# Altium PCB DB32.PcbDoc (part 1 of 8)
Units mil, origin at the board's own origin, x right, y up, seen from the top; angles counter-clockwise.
Board outline 3236.22 x 4456.69 mil, 8 copper layers (Top Layer, MidLayer1, MidLayer2, GND-Layer5, MidLayer3, VCC, MidLayer4, Bottom Layer), stack 61.8 mil thick; 207 components, 474 nets, 1777 pads, 1474 vias.
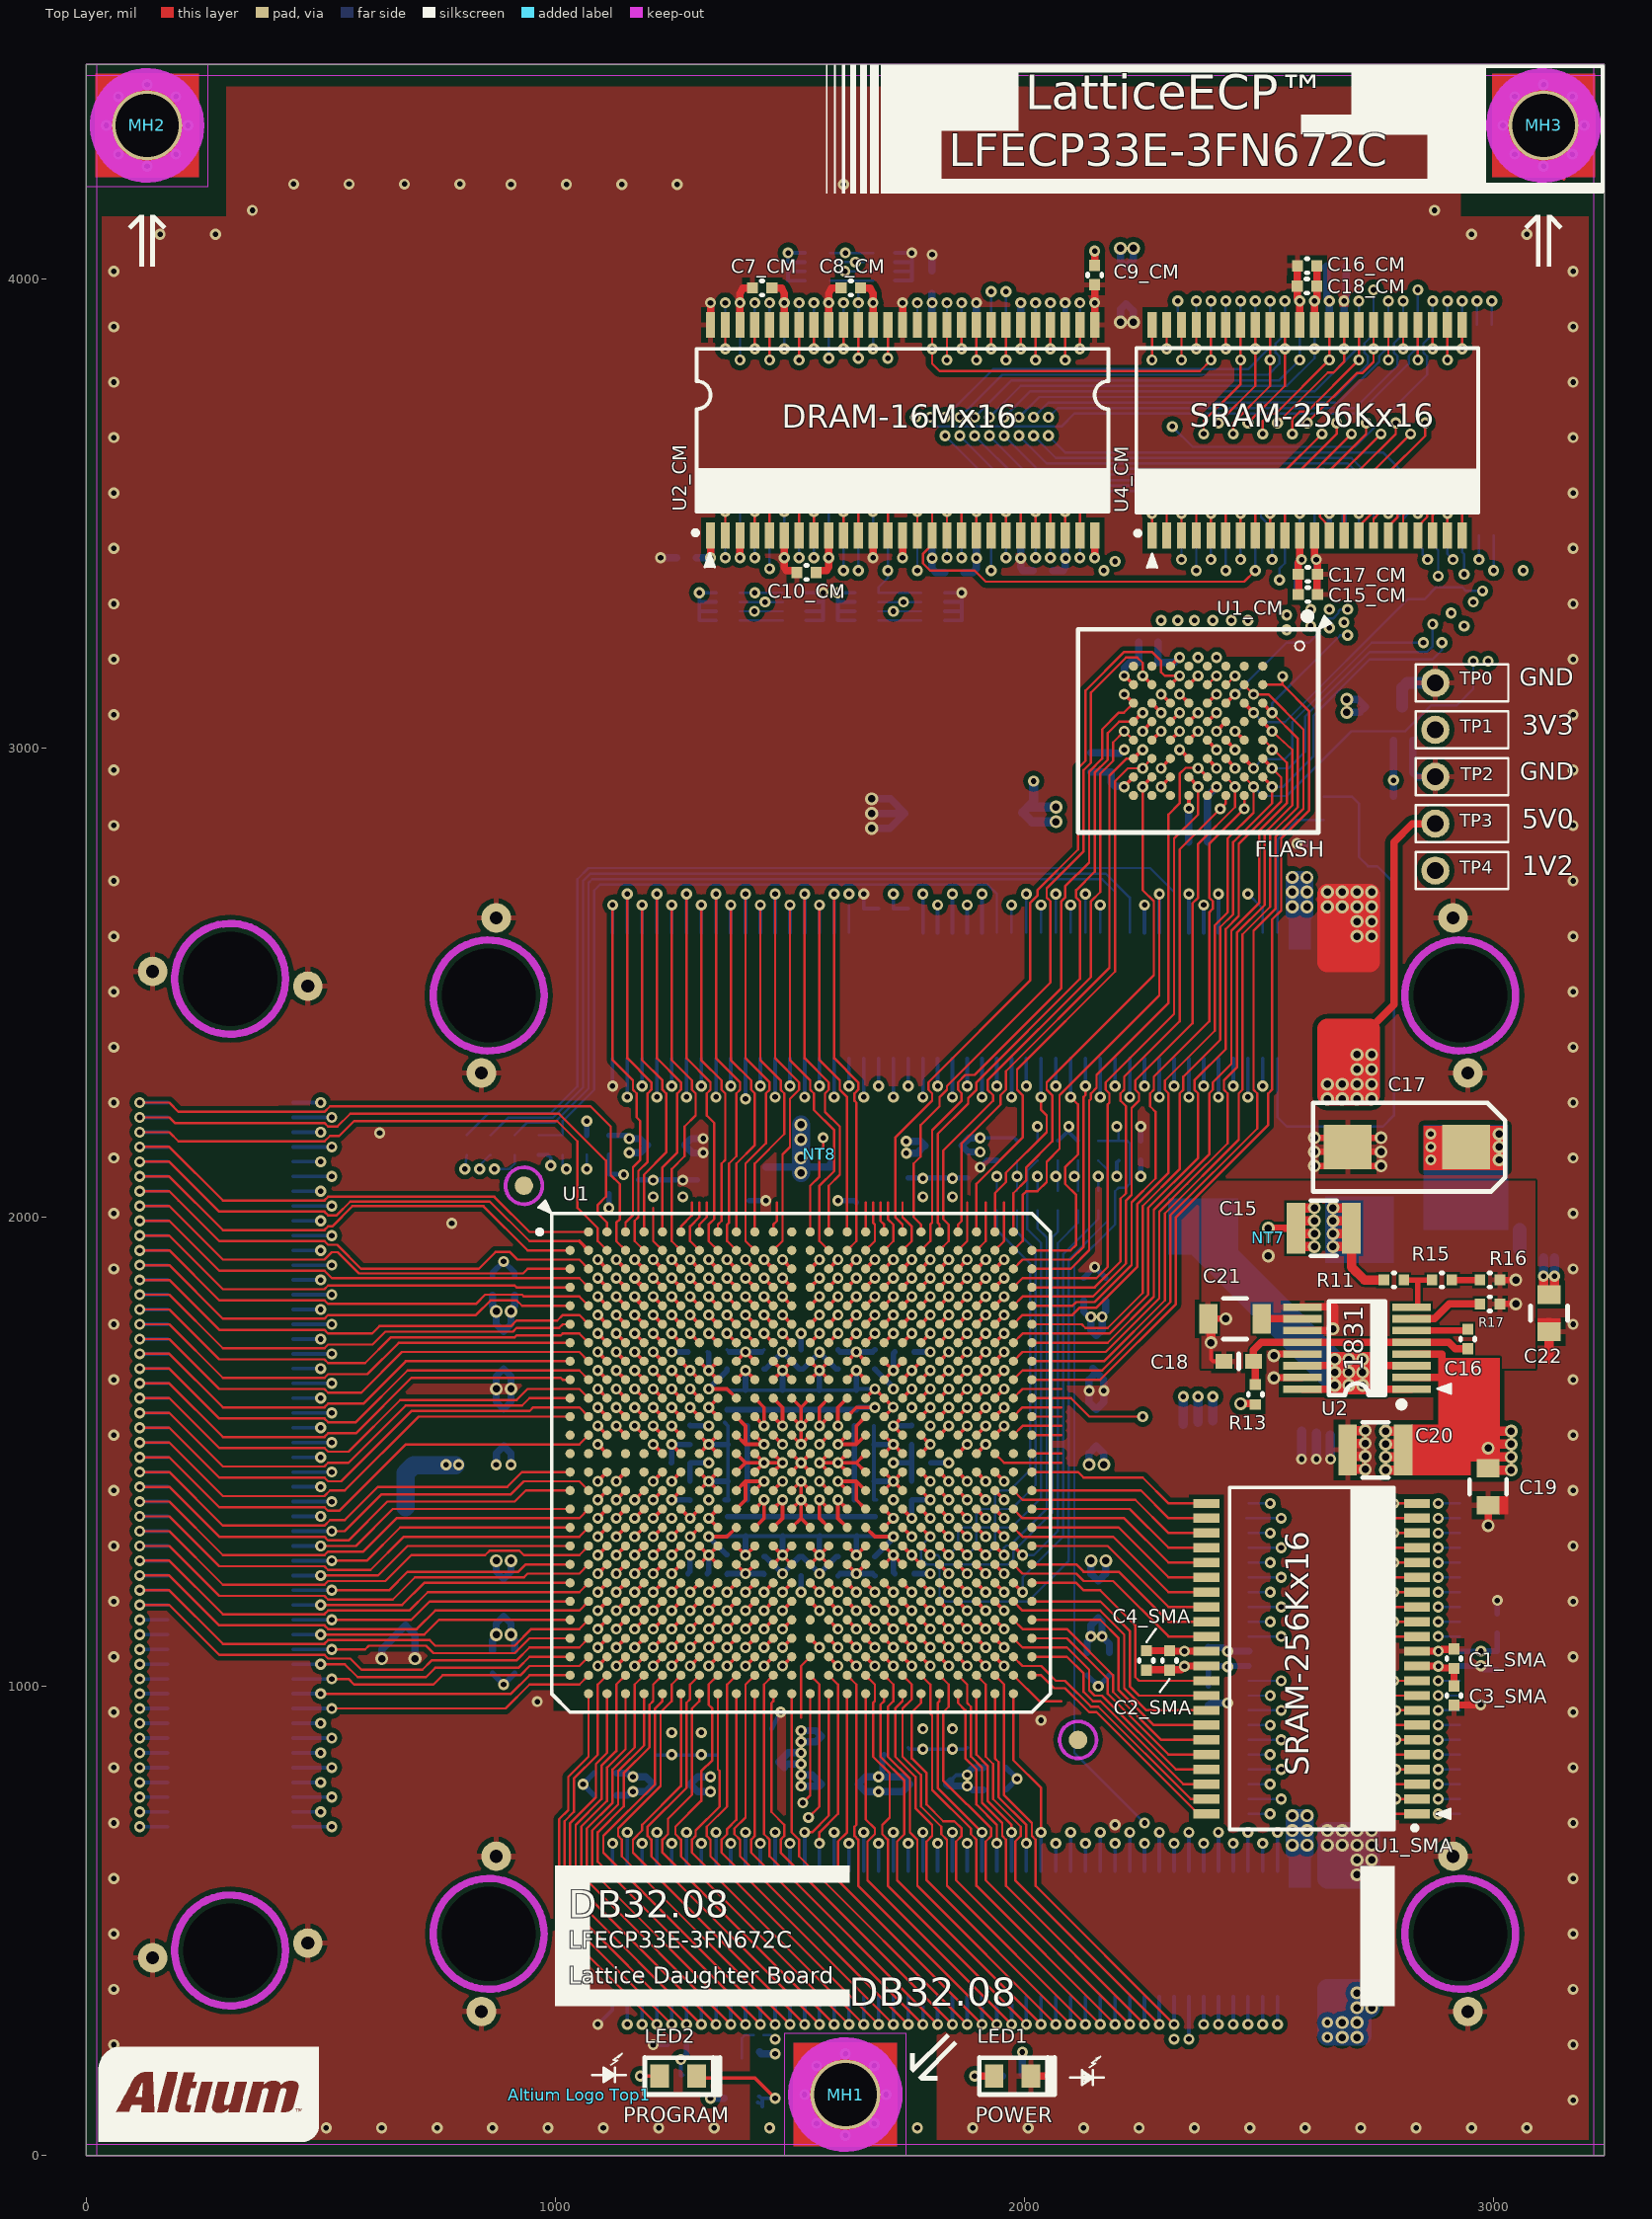
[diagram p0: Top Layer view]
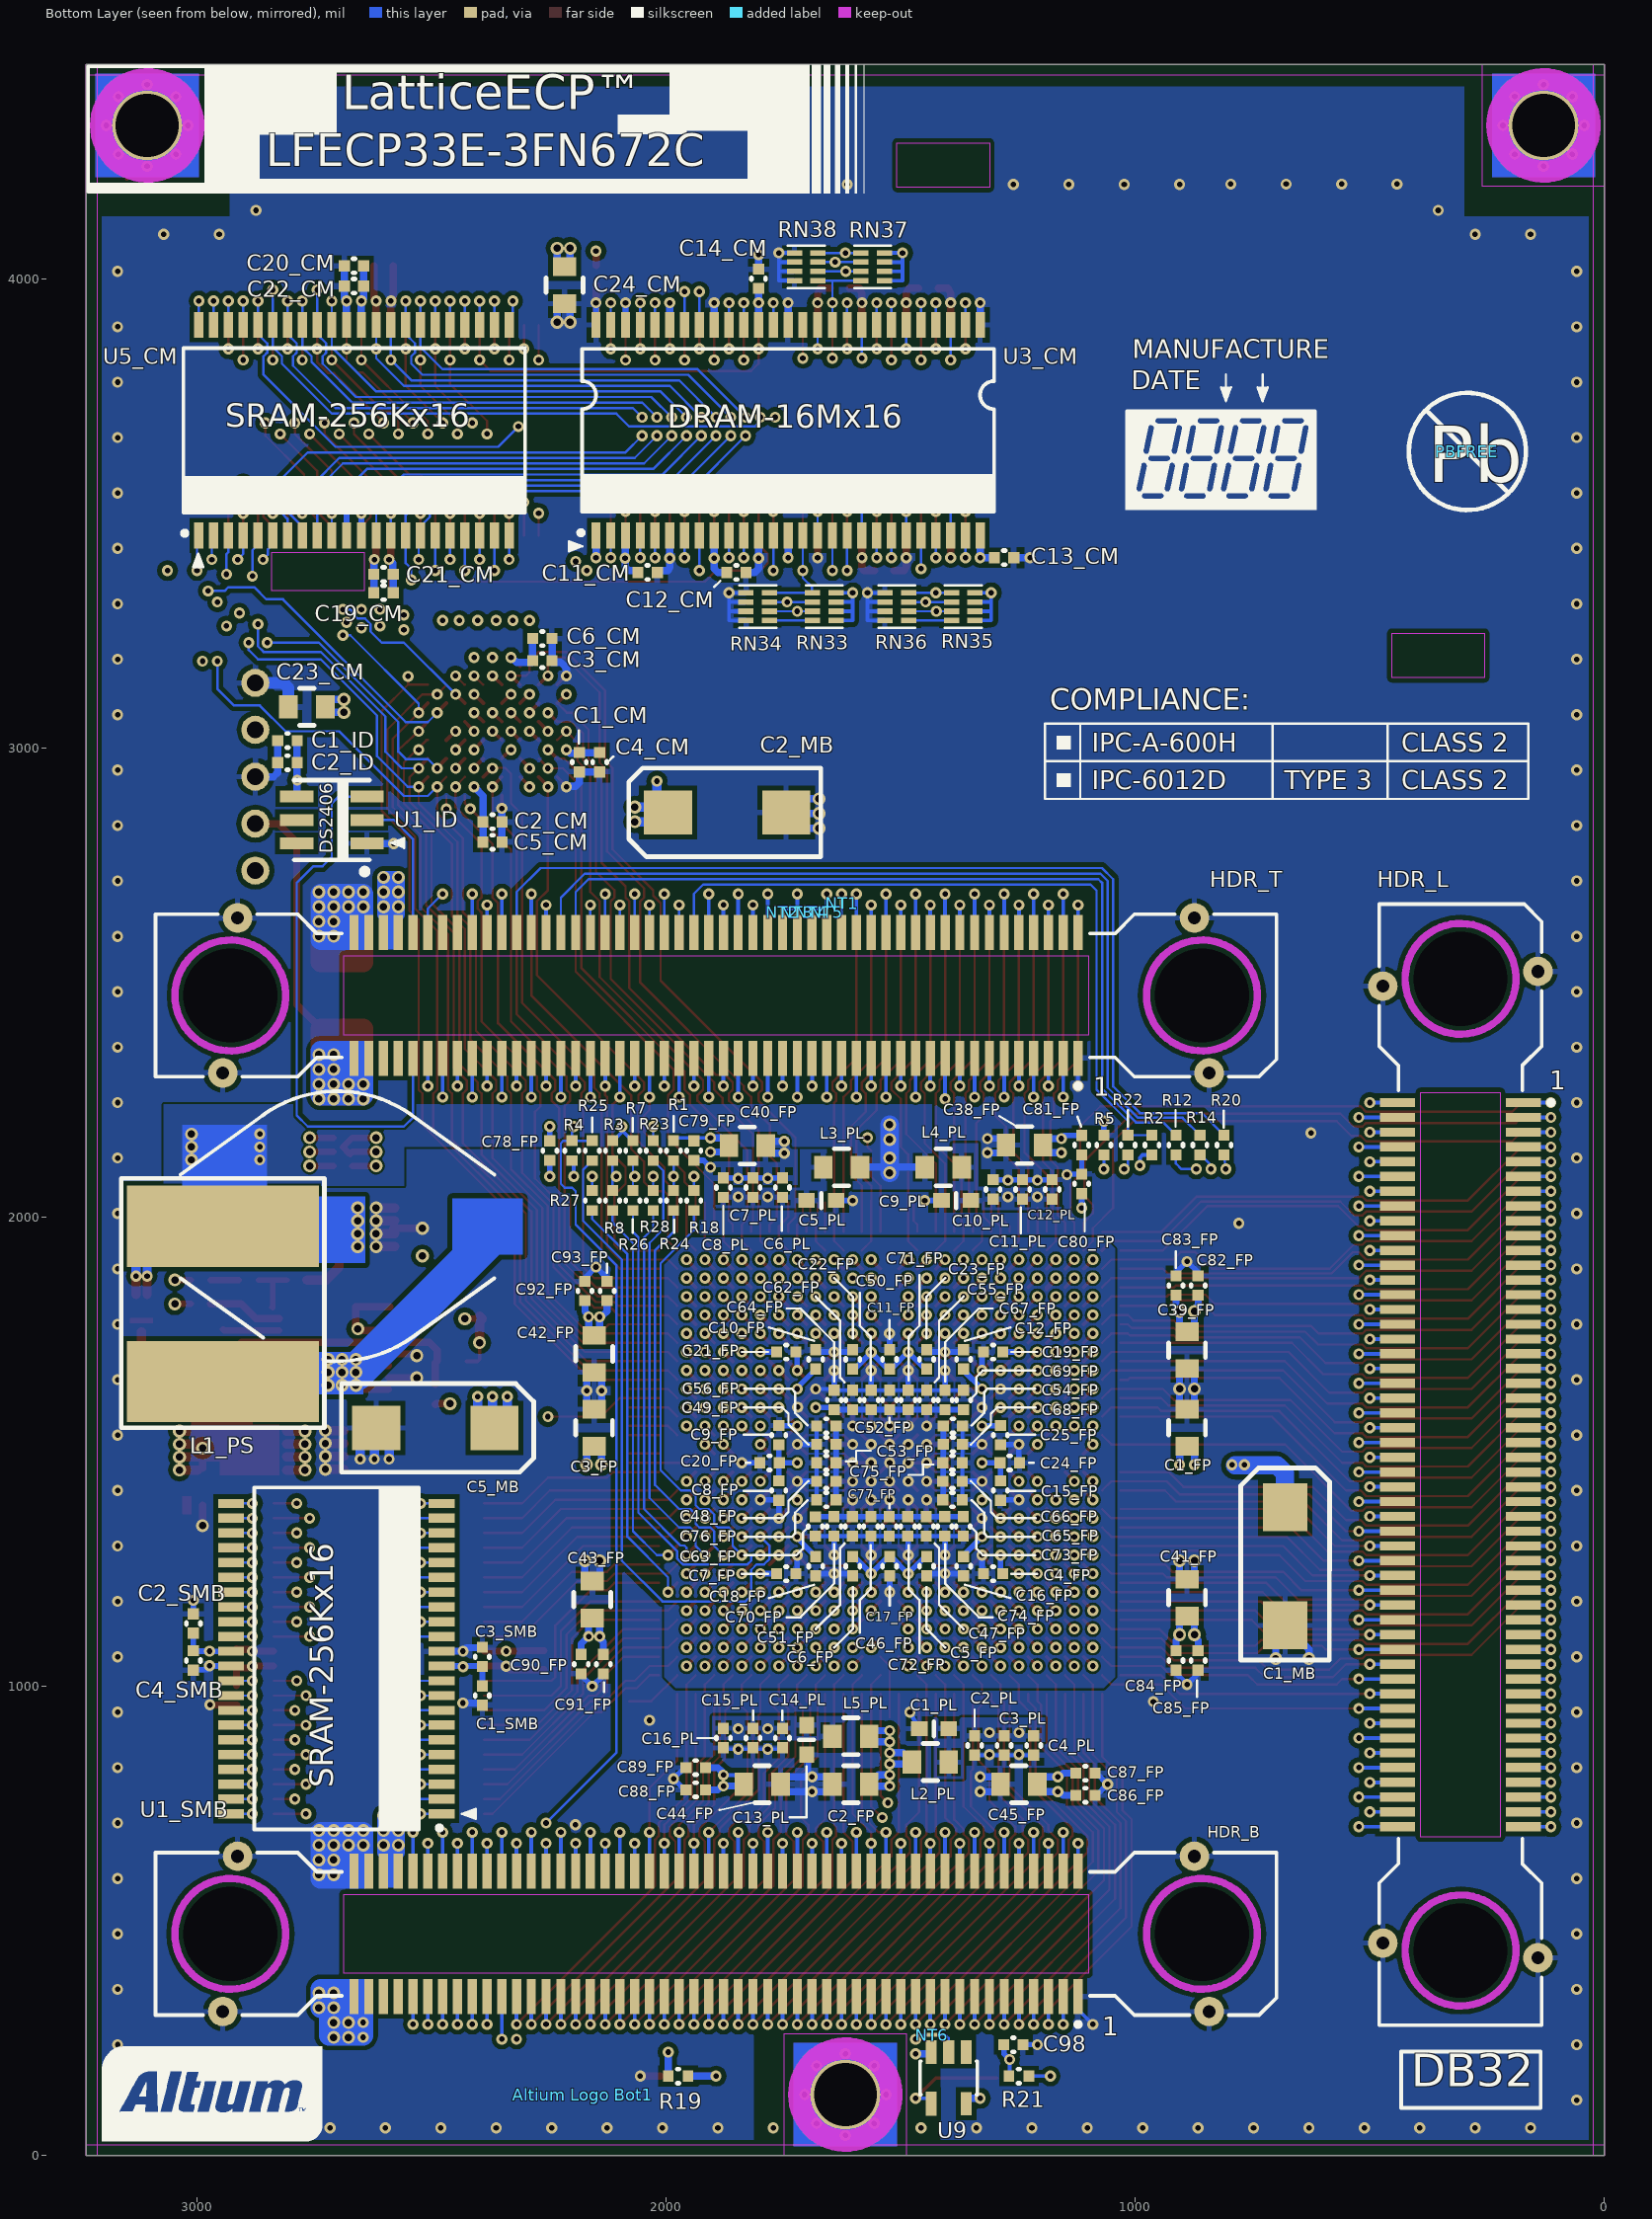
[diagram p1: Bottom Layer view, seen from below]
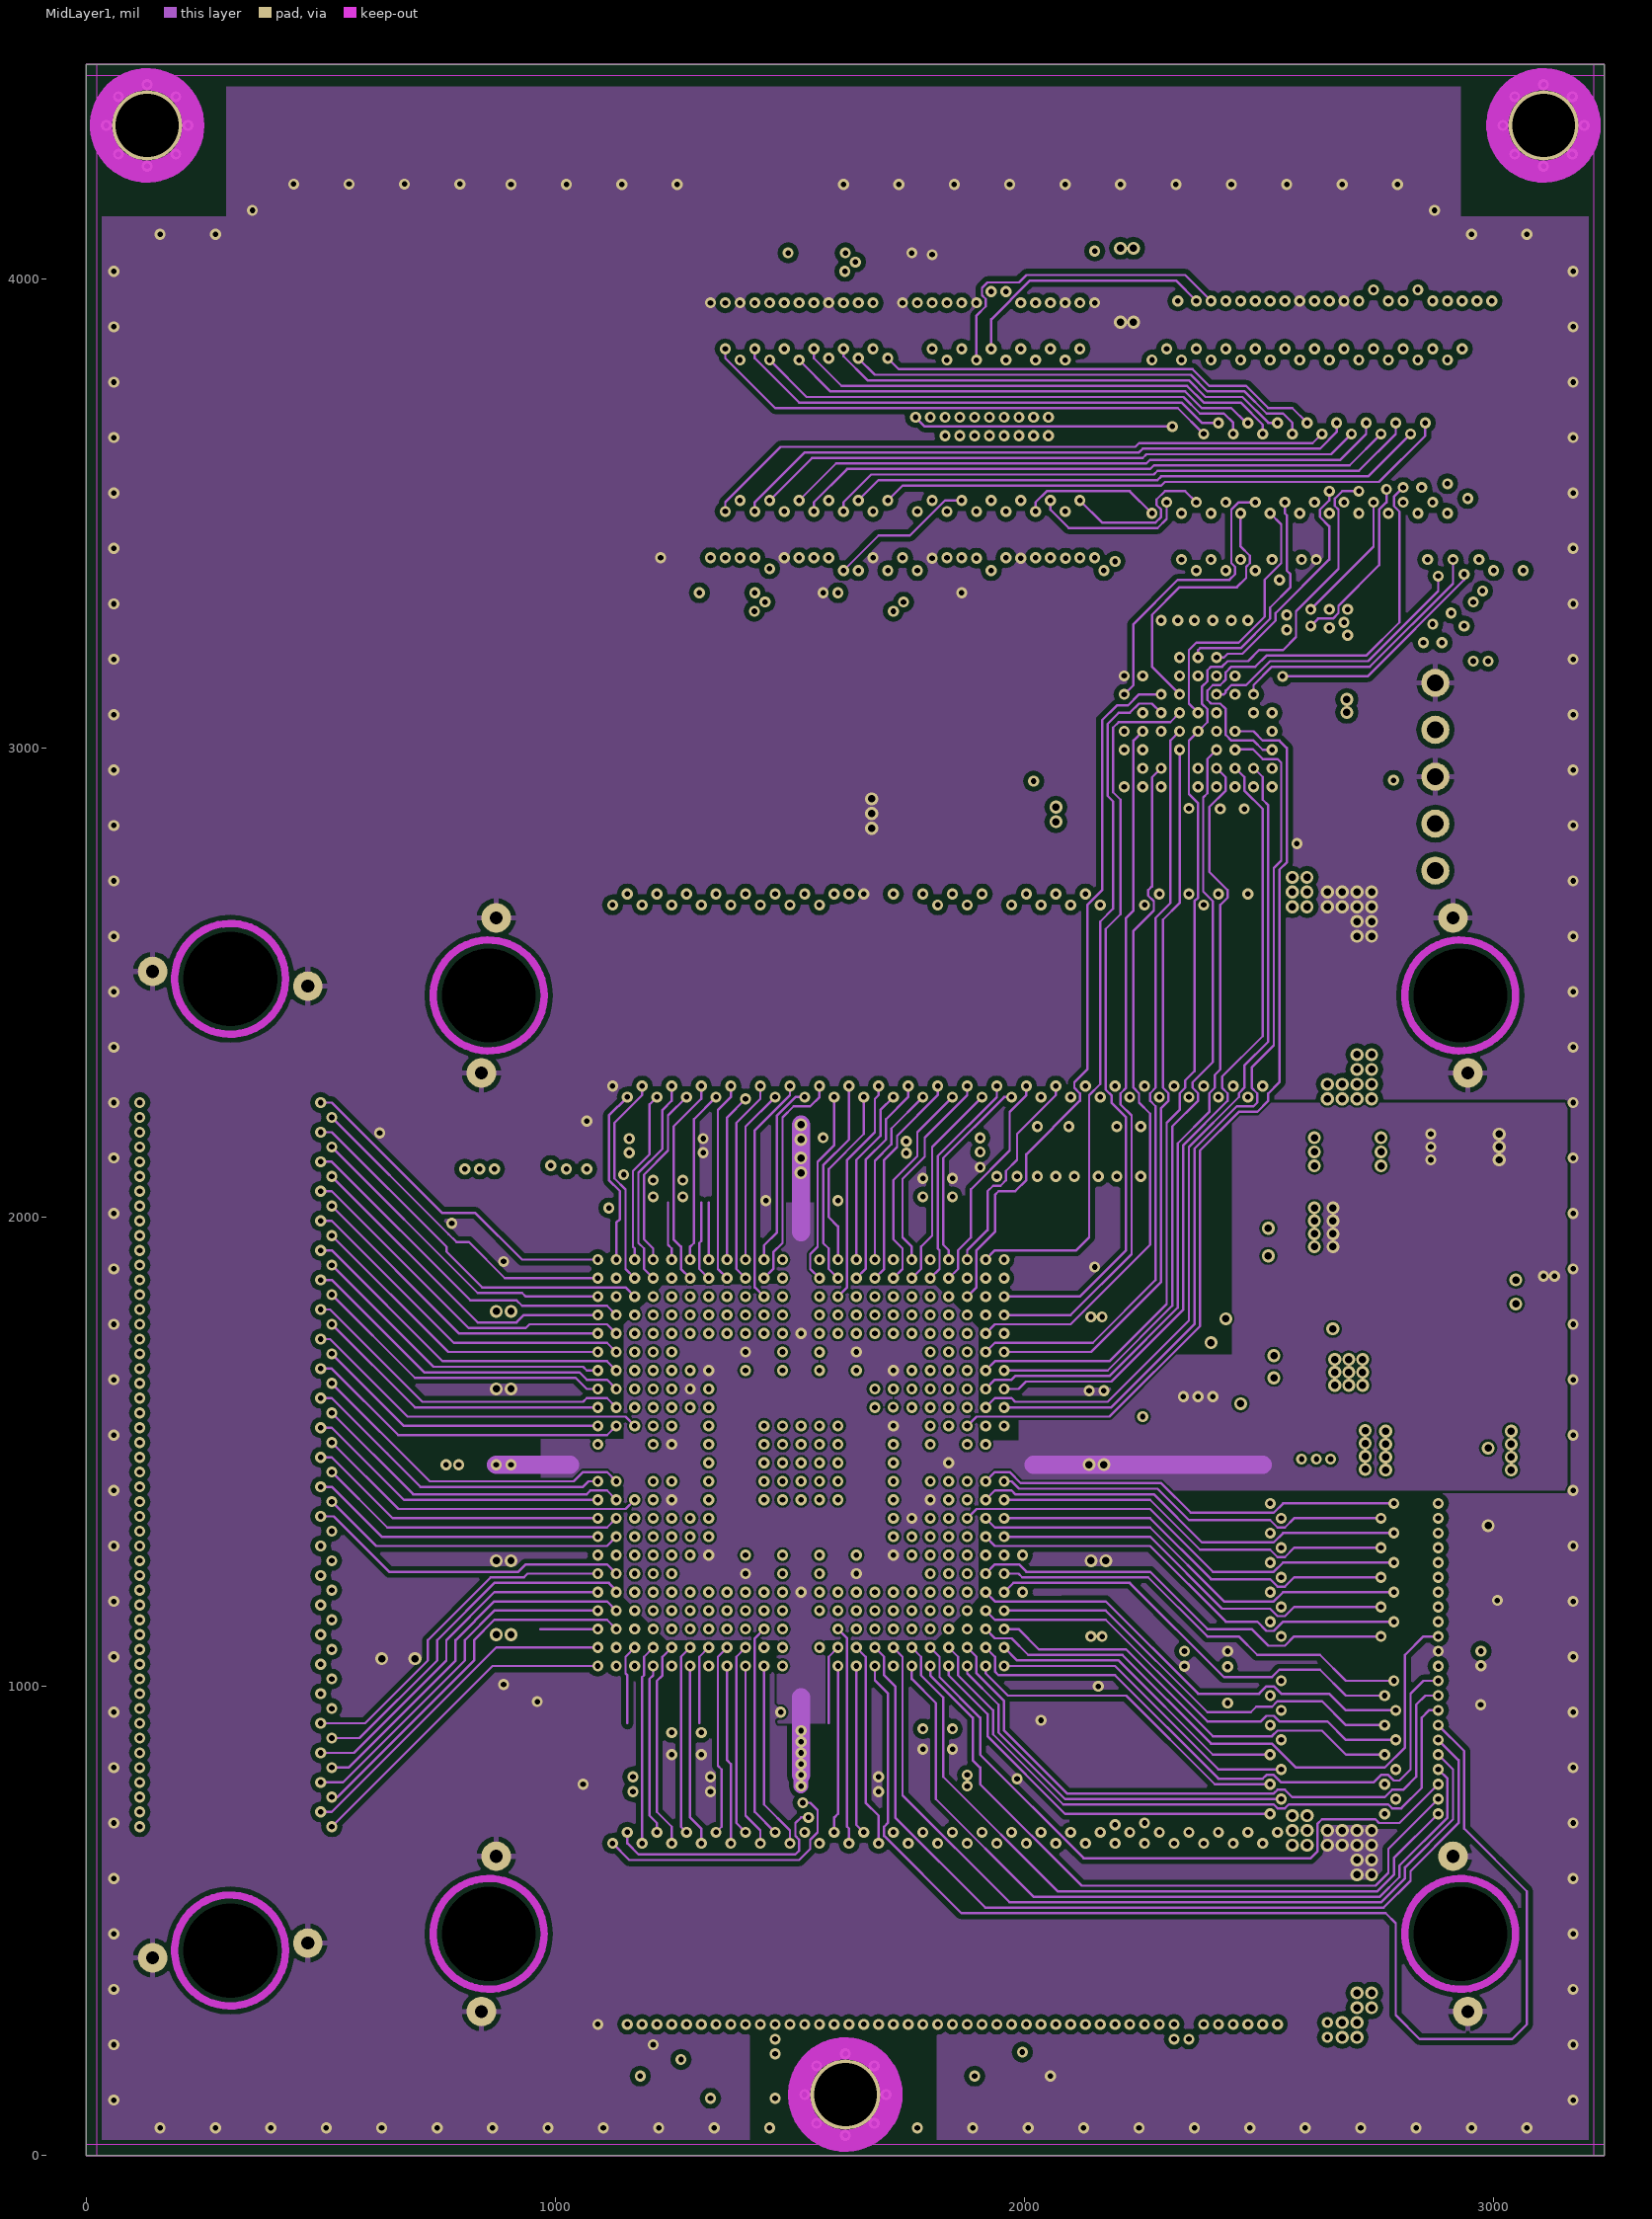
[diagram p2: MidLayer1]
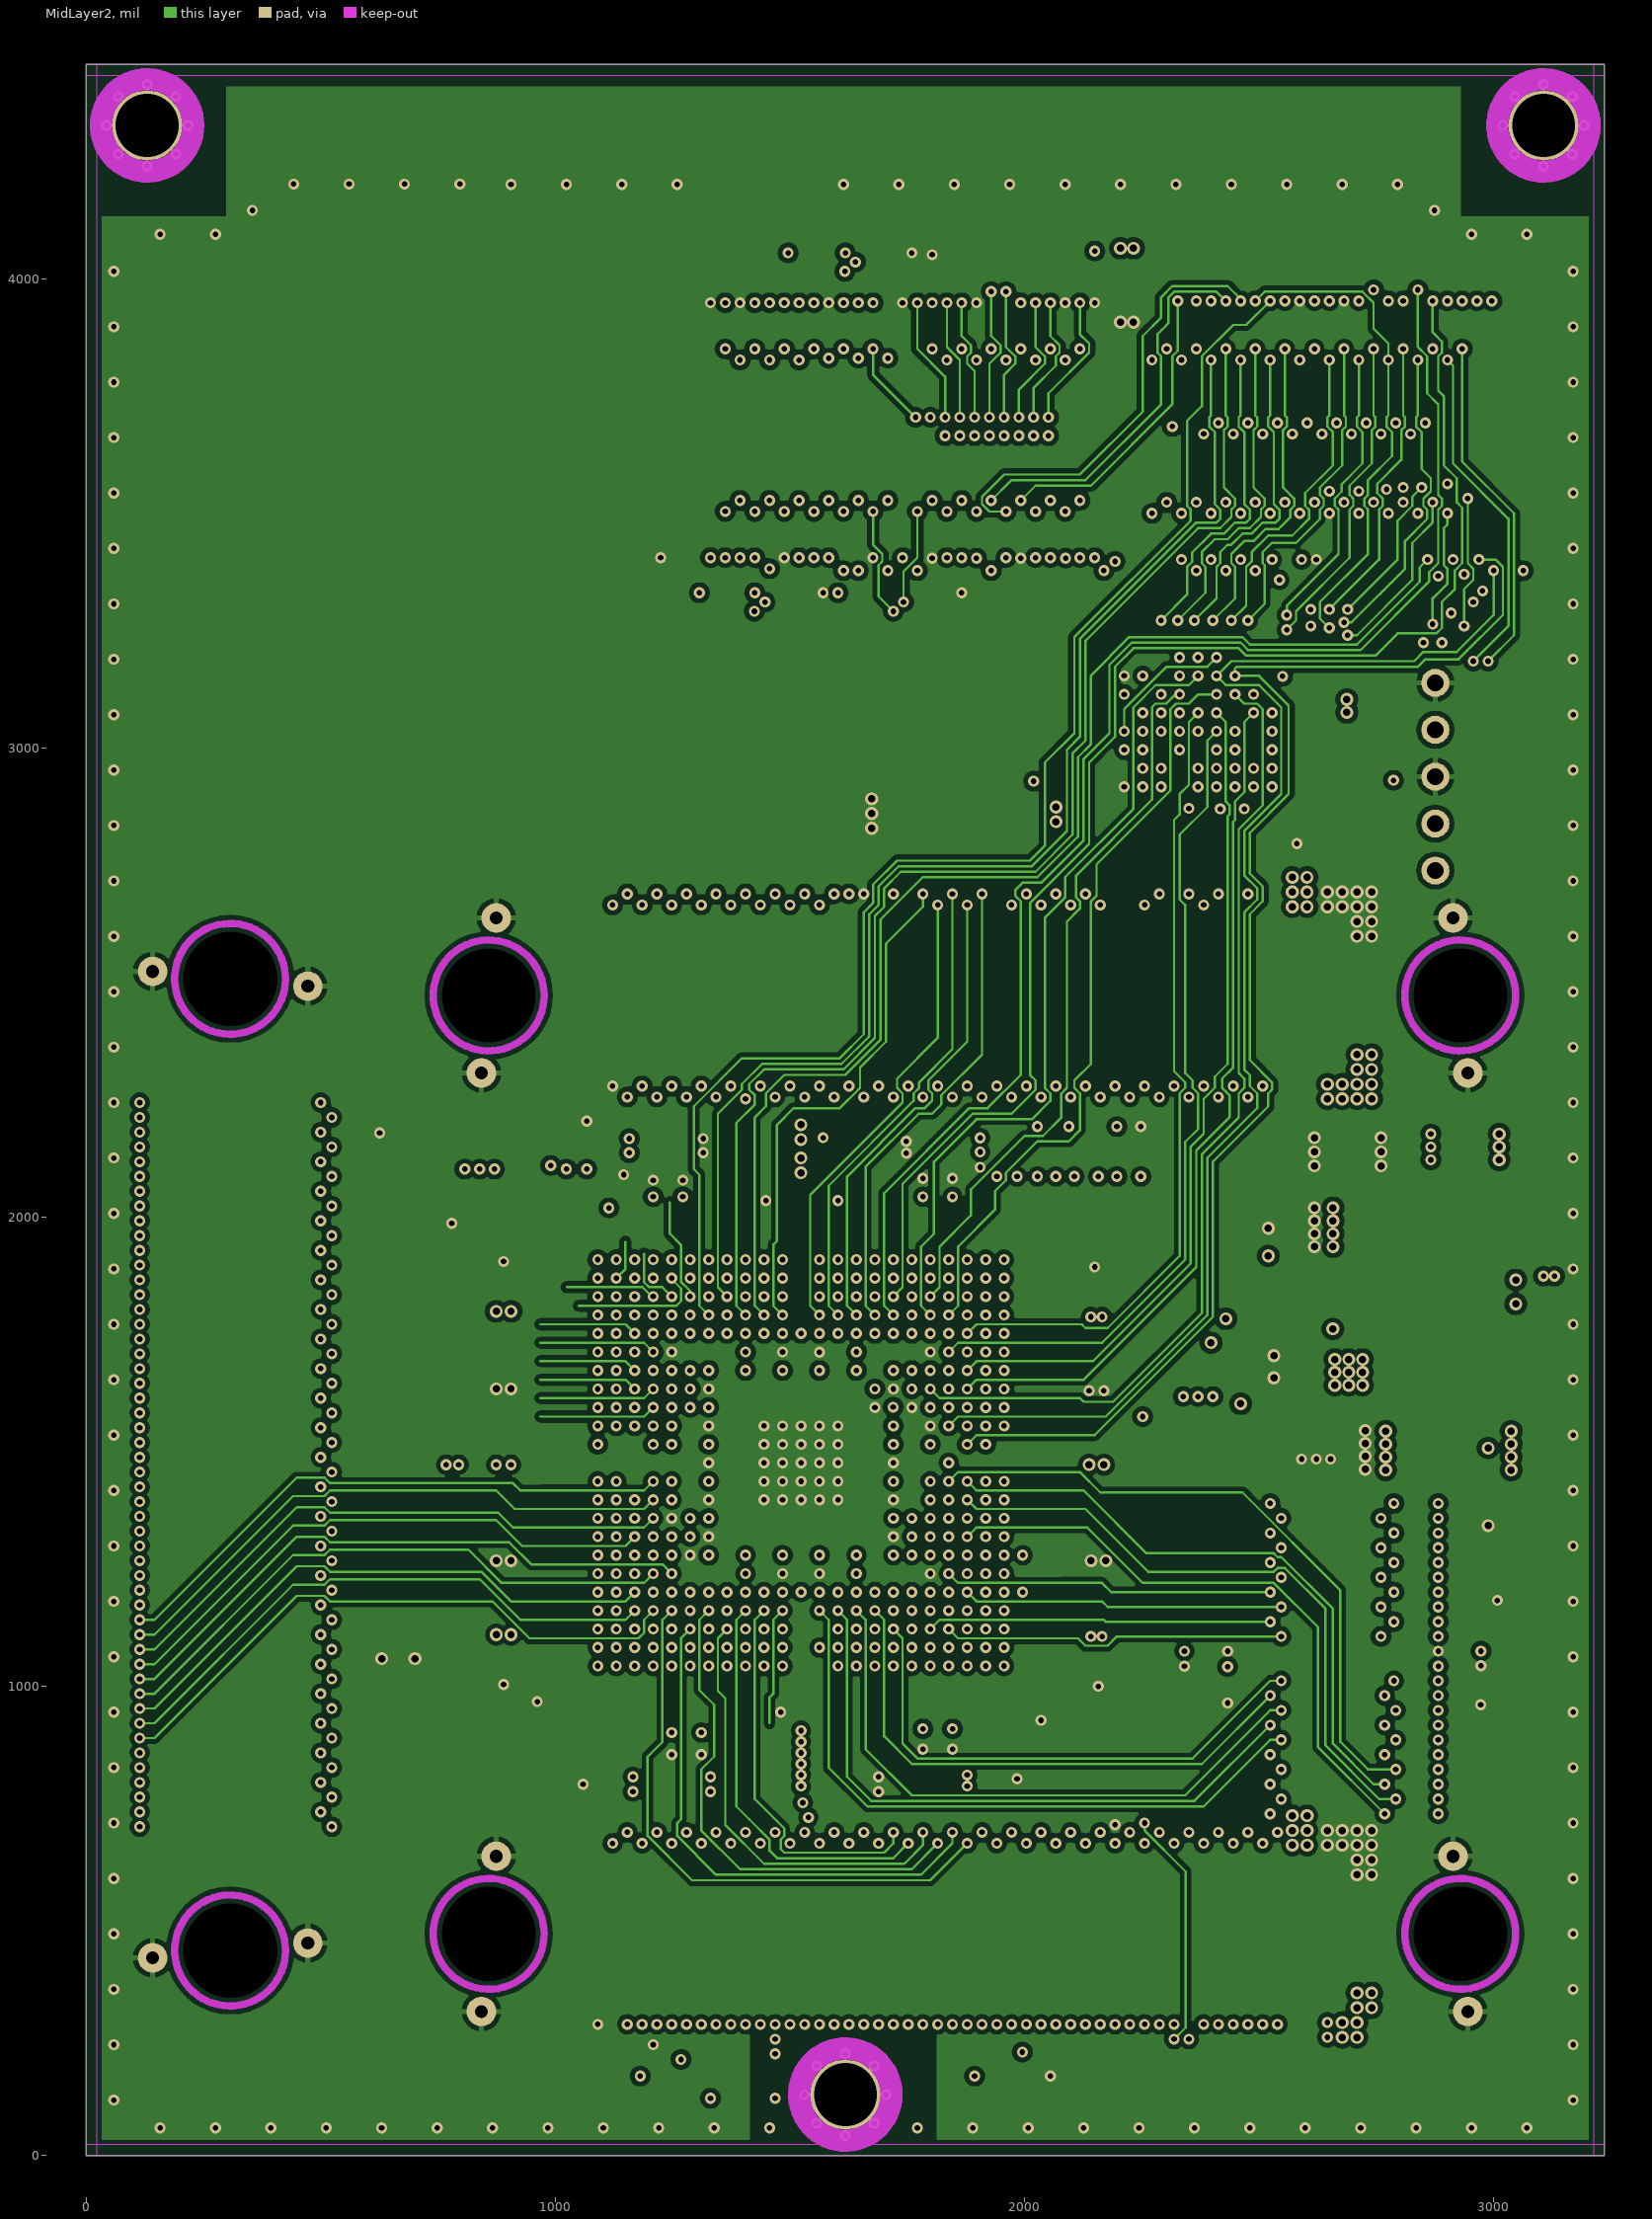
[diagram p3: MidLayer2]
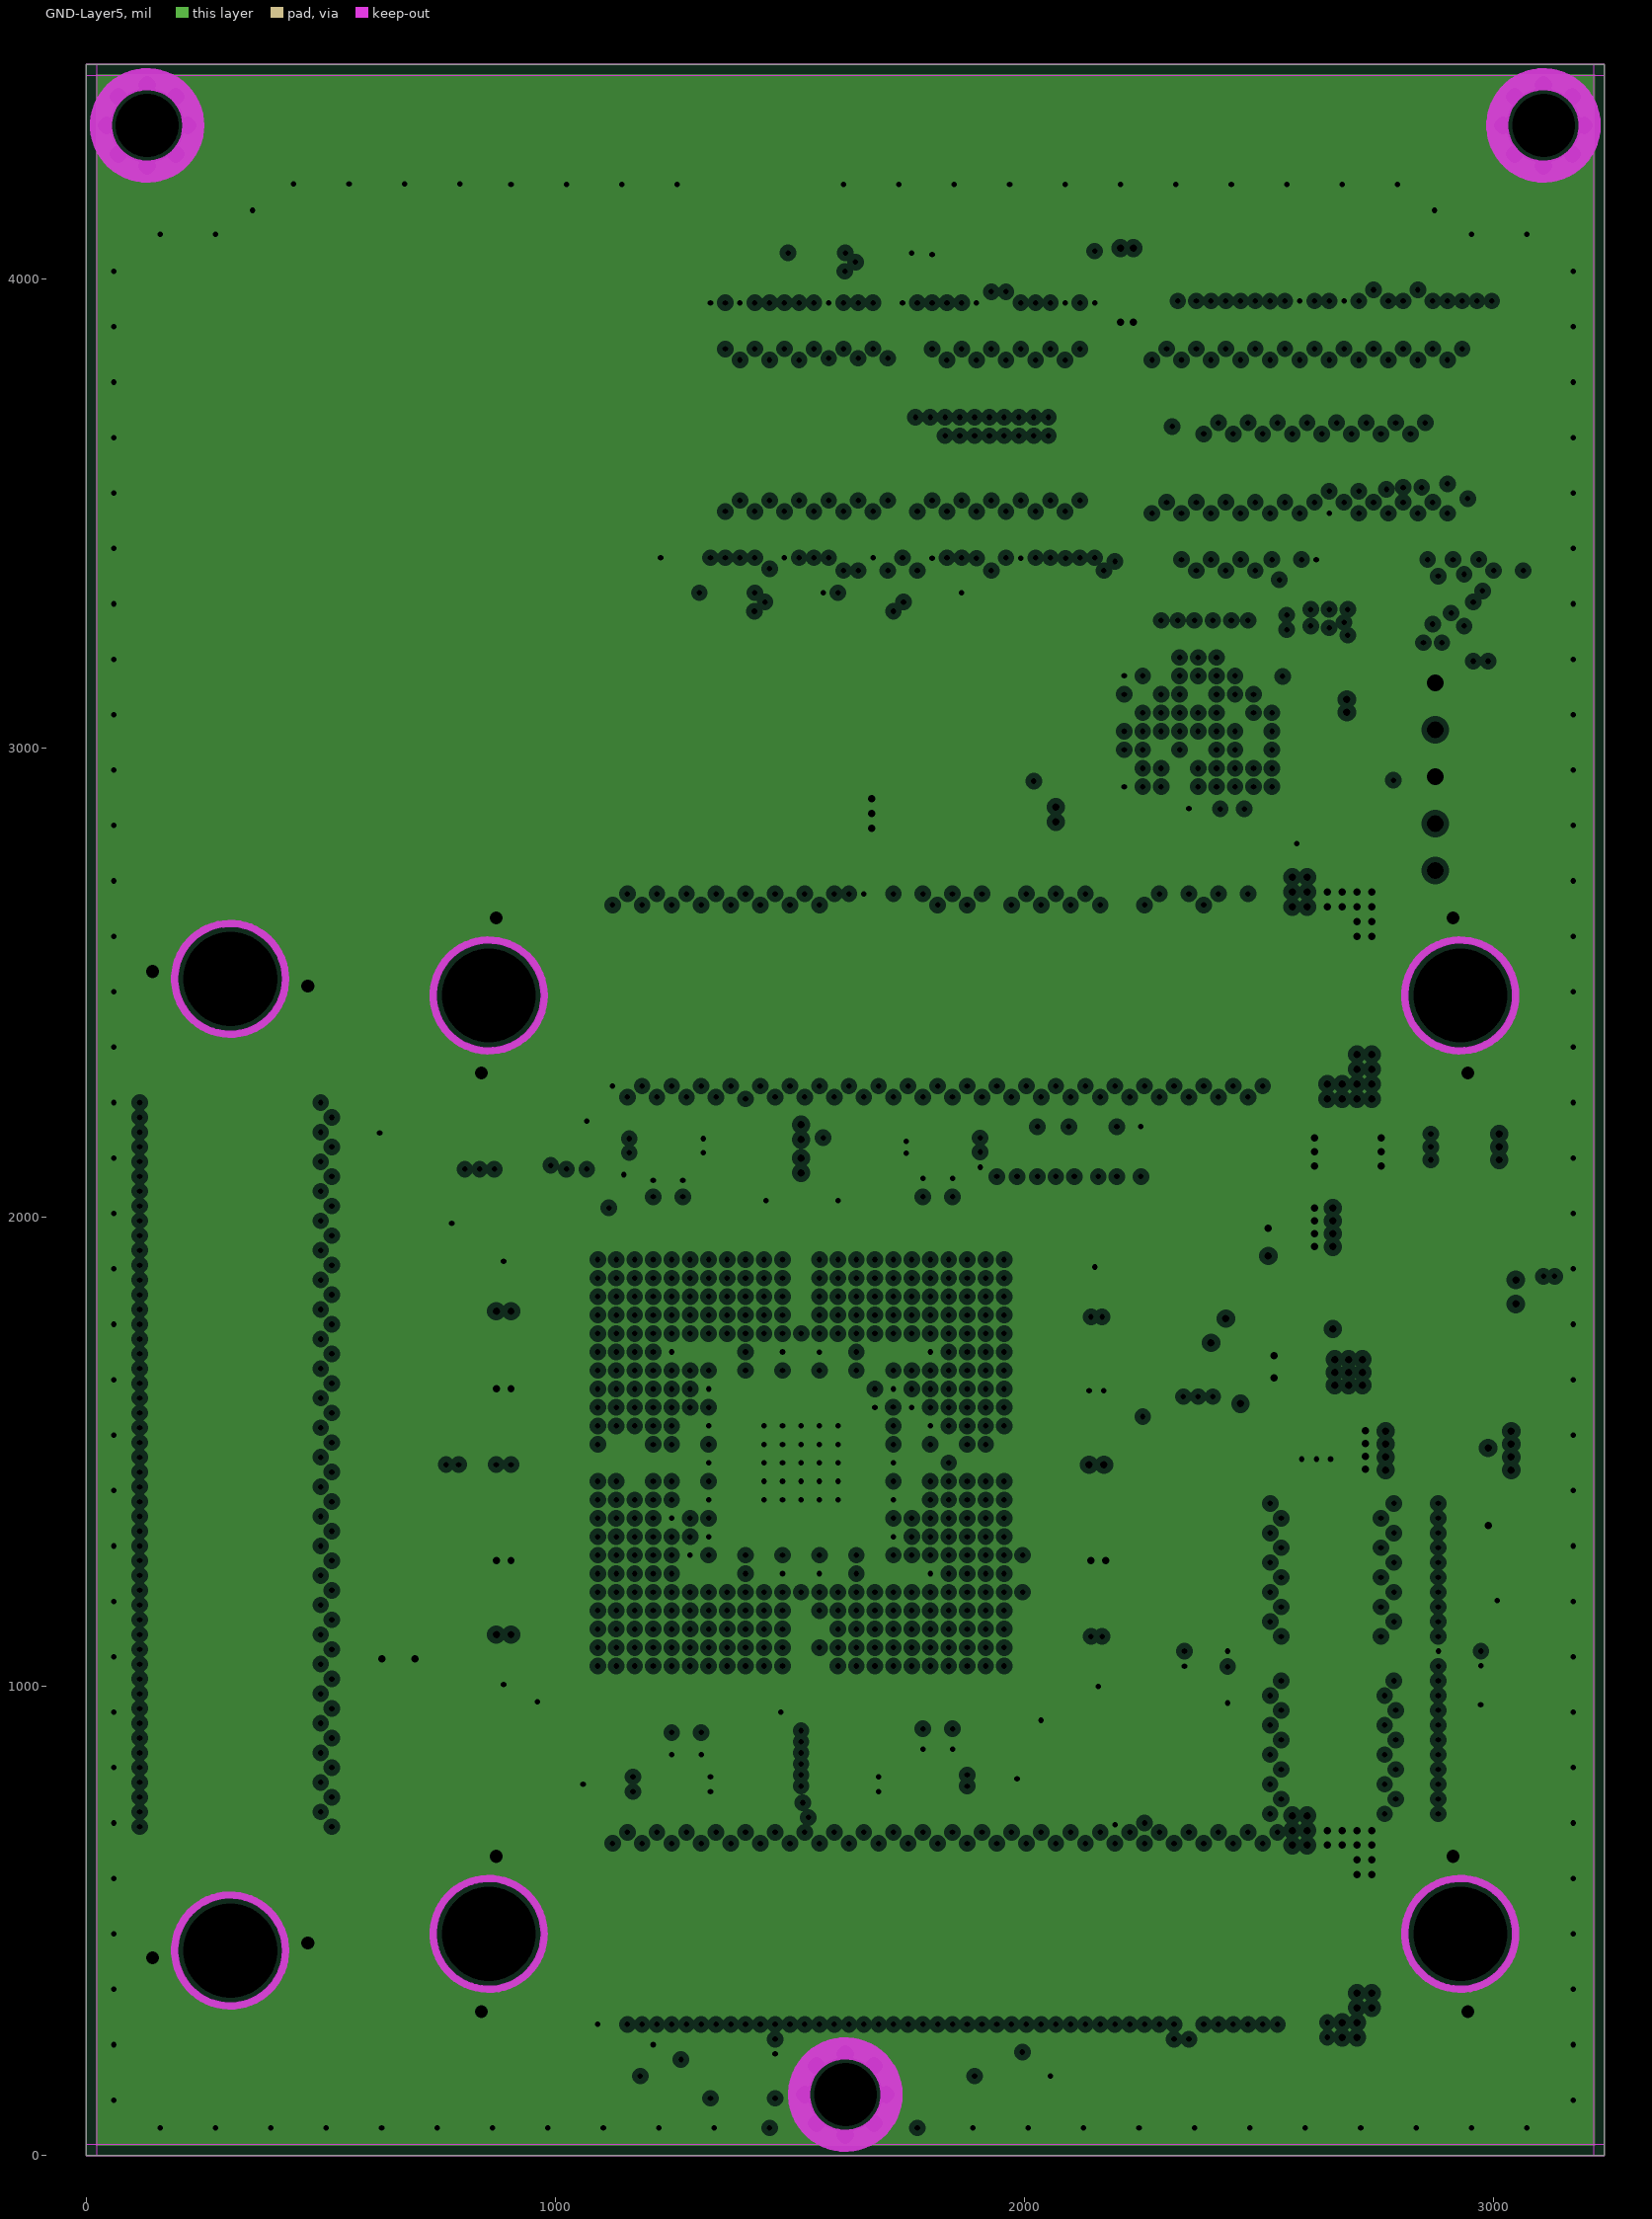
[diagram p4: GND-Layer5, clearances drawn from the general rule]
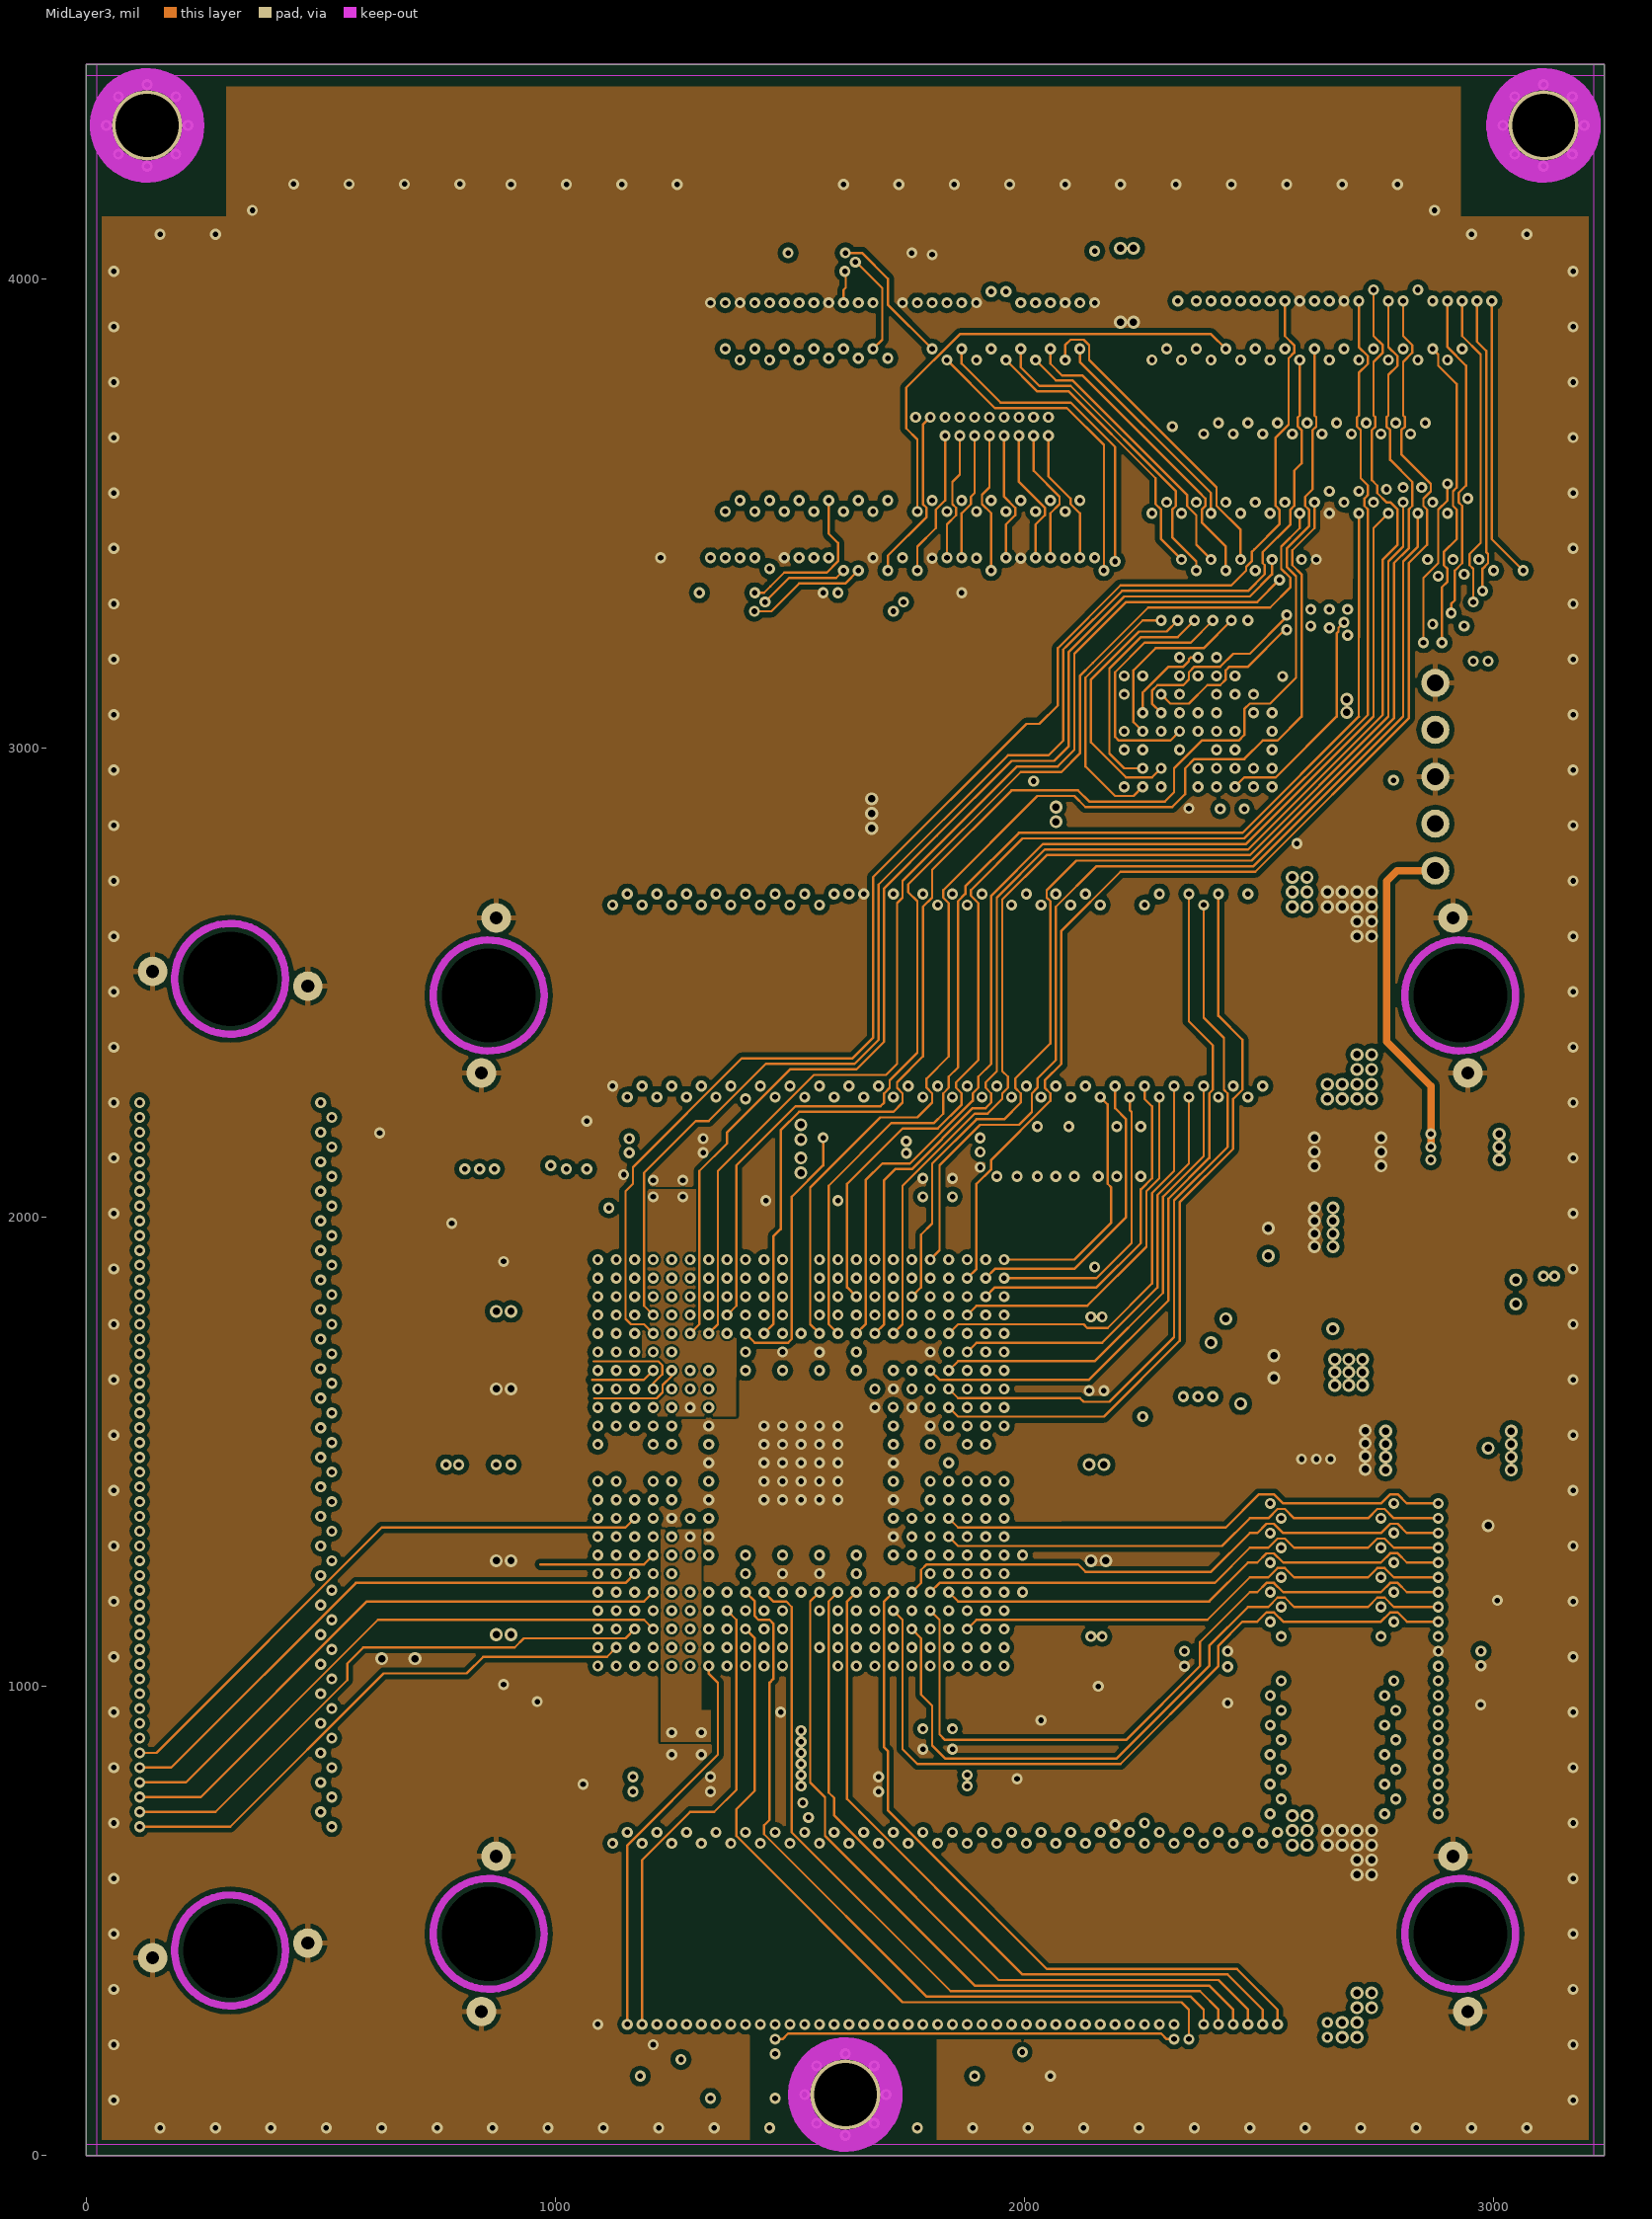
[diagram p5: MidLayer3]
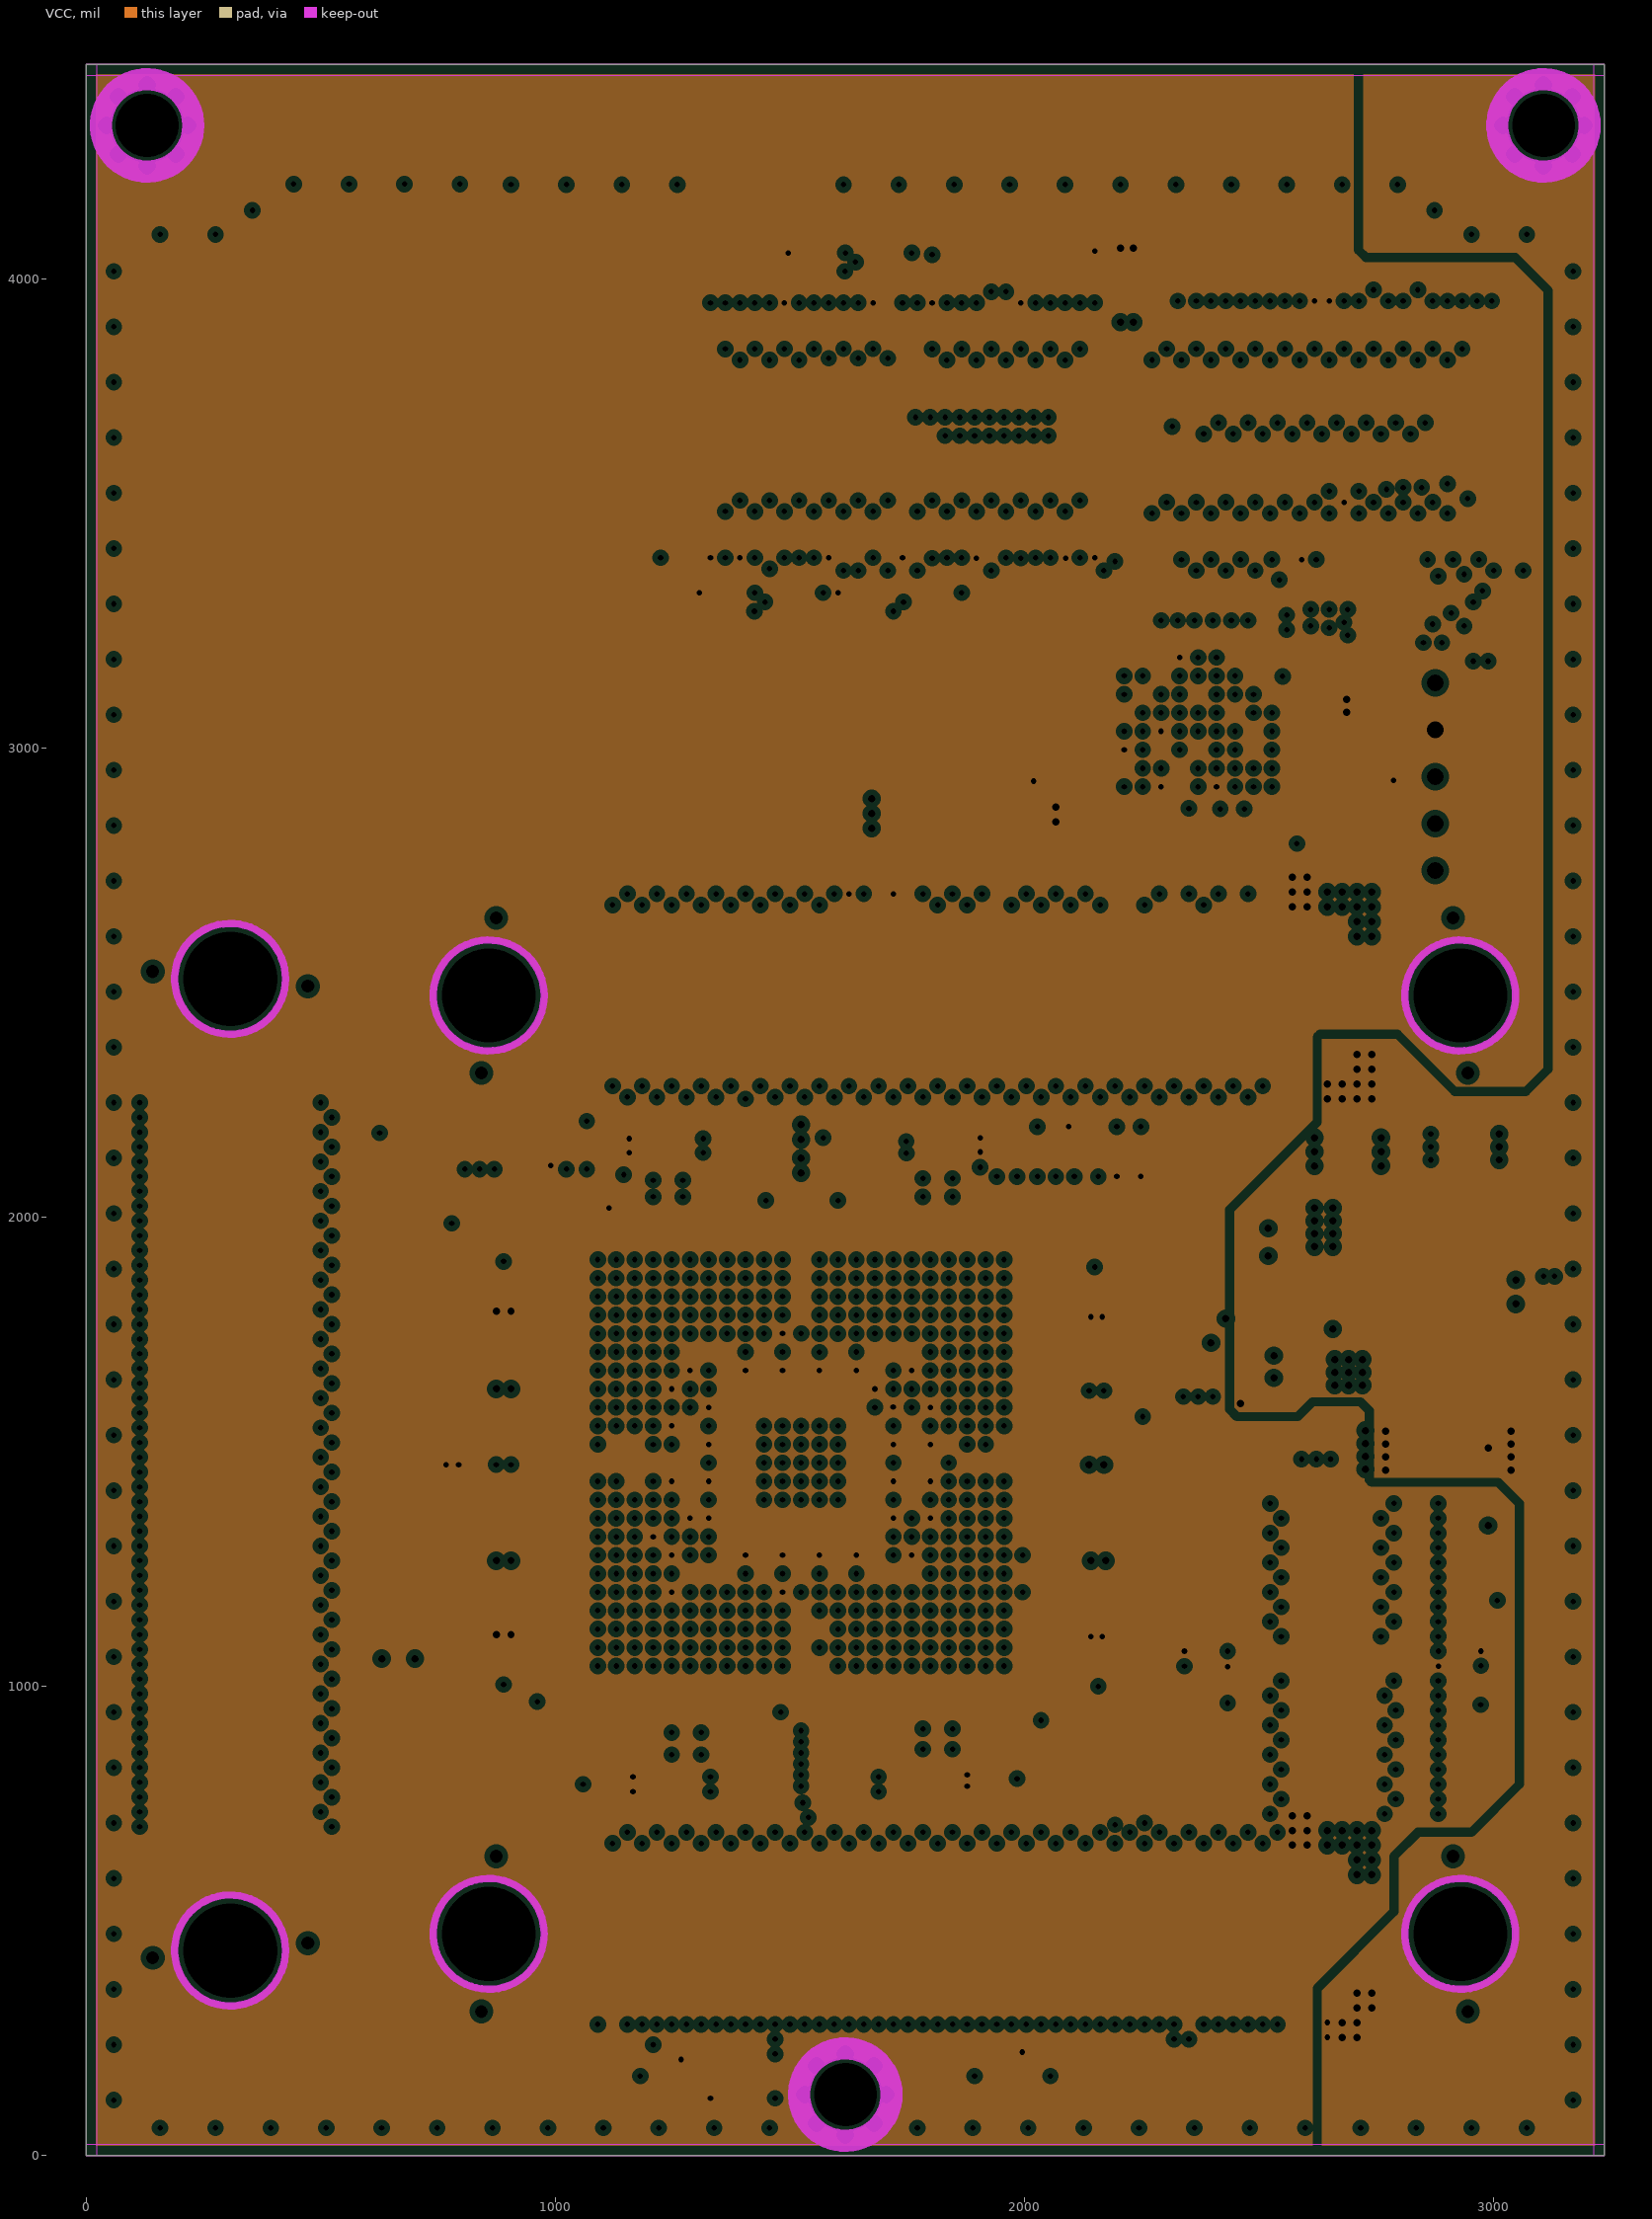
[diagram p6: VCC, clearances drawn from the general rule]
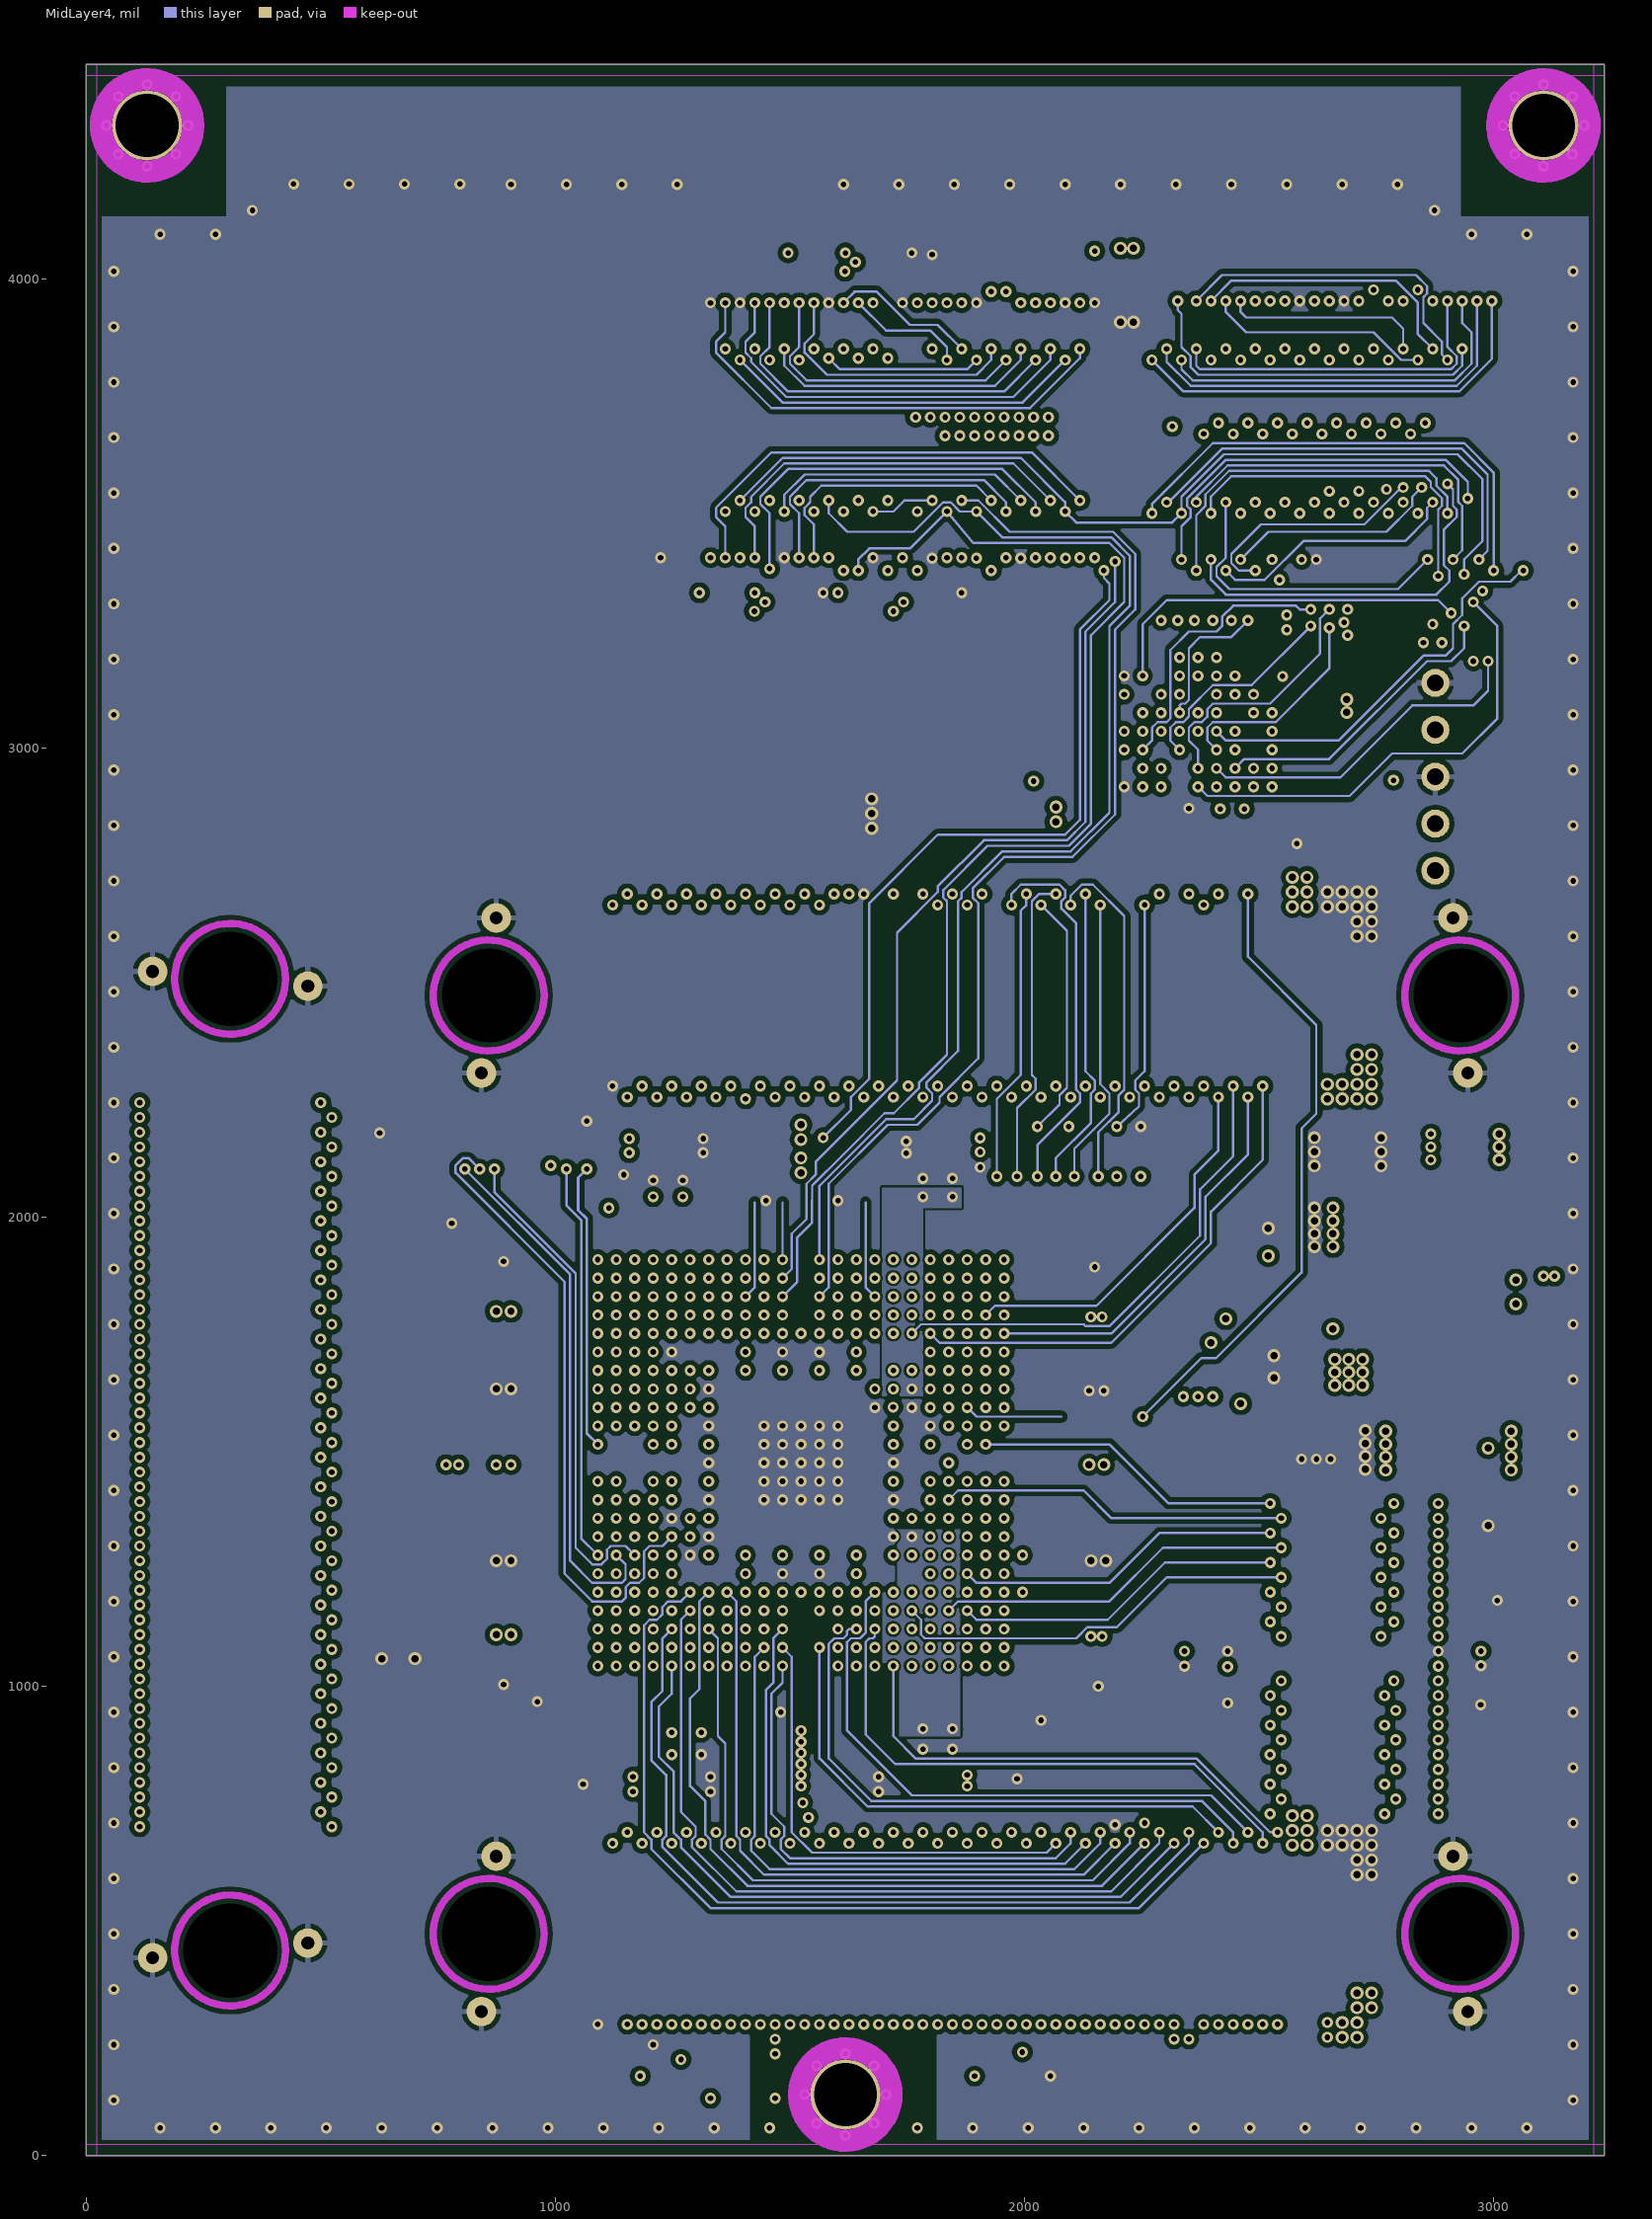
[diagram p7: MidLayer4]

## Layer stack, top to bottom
Top Layer: signal copper 1.7
Dielectric: prepreg 5, FR-4, Dk 4.2
MidLayer1: signal copper 1.4
Dielectric: core 10, FR-4, Dk 4.2
MidLayer2: signal copper 1.4
Dielectric: prepreg 5, FR-4, Dk 4.2
GND-Layer5: plane copper 1.4, net GND
Dielectric: core 10, FR-4, Dk 4.2
MidLayer3: signal copper 1.4
Dielectric: prepreg 5, FR-4, Dk 4.2
VCC: plane copper 1.4, net (Multiple Nets)
Dielectric: core 10, FR-4, Dk 4.2
MidLayer4: signal copper 1.4
Dielectric: prepreg 5, FR-4, Dk 4.2
Bottom Layer: signal copper 1.7

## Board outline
0,0 0,4456.69 1523.62,4456.69 3236.22,4456.69 3236.22,0

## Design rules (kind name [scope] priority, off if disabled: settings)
Clearance Clearance_Poly_Tight [InNamedPolygon('FPGAPWR-BL-GND') Or InnamedPolygon('FPGAPWR-TL-GND') Or InNamedPolygon('FPGAPWR-BL-1V2') Or InNamedPolygon('FPGAPWR-BL-3V3') Or InNamedPolygon('FPGAPWR-ML1-1V2') Or InNamedPolygon('FPGAPWR-TL-1V2') Or InNamedPolygon('1V2-CONNECT-TO-L1-C17' ) Or InNamedPolygon('VCCA_PLL1_BL') Or InNamedPolygon('VCCA_PLL1_MID3') Or InNamedPolygon('VCCA_PLL2_BL') Or InNamedPolygon('VCCA_PLL2_MID4') Or InNamedPolygon('VCCA_PLL3_BL') Or InNamedPolygon('VCCA_PLL3_MID3') Or InNamedPolygon('VCCA_PLL4_BL') Or InNamedPolygon('VCCA_PLL4_MID4') Or InNamedPolygon('top-layer-1V2') Or InNamedPolygon('1V2-BL') Or InNamedPolygon('LX') Or InNamedPolygon('AGND-TOP')] p1: gap=5
Clearance Clearance_Polygon [InPolygon] p2: gap=10
Clearance "Pad-Pad Clearance Same Net" [IsPad vs IsPad] p3: gap=5
Clearance "General Clearance" [All] p4: gap=5
ComponentClearance [All] p1 off: gap=7.87 collisioncheckmode=3 verticalgap=10 showdistances=FALSE
DiffPairsRouting [All] p1: maxlimit=5 minlimit=5 mostfreqgap=5 maxuncoupledlength=200
FabricationTestPointUsage TestPointUsage [All] p1 off: valid=0 allowmultiple=FALSE
FabricationTestpoint Testpoint [All] p1 off: side=3 testpointundercomponent=TRUE minsize=40 maxsize=100 preferedsize=60 minholesize=0 maxholesize=40 preferedholesize=32 testpointgrid=1 allowsidetop=TRUE allowsidebottom=TRUE usegrid=TRUE gridtolerance=0.01
HoleSize [All] p1: absolutevalues=TRUE maxlimit=204.72 minlimit=7.87 maxpercent=80.000 minpercent=20.000
HoleToHoleClearance [All] p1: gap=4 allowstackedmicrovias=TRUE
MatchedLengths DiffPair_MatchedLengths [(IsDifferentialPair And (Name = 'DIFF_RX1'))] p1: tolerance=1000 checknetsindiffpair=TRUE checkdiffpairvsdiffpair=TRUE checkothers=TRUE
MinimumAnnularRing MinimumAnnularRing_NonPlated [(ObjectKind = 'Pad') And (HoleDiameter >= '0.7') And (PadIsPlated = 'False')] p1: minimumring=-196.85
MinimumAnnularRing [All] p2: minimumring=5.91
MinimumSolderMaskSliver [All] p1: minsoldermaskwidth=4
PlaneClearance [All] p1: clearance=11.81
PlaneConnect [All] p1: planeconnectstyle=Direct reliefexpansion=19.68 reliefentries=4 reliefconductorwidth=9.84 reliefairgap=9.84
PolygonConnect PolygonConnect_Via [IsVia] p1: connectstyle=Direct reliefconductorwidth=10 reliefentries=4 polygonreliefangle="90 Angle"
PolygonConnect "PolygonConnect - Heatsink" [(HasFootprint('TO-263') AND InNet('VCCINT'))] p2: connectstyle=Direct reliefconductorwidth=10 reliefentries=4 polygonreliefangle="90 Angle"
PolygonConnect [All] p3: connectstyle=Relief reliefconductorwidth=11.81 reliefentries=4 polygonreliefangle="90 Angle"
RoutingLayers [All] p1: top layer_v5=FALSE mid layer 1_v5=FALSE mid layer 2_v5=FALSE mid layer 3_v5=FALSE mid layer 4_v5=FALSE bottom layer_v5=FALSE
RoutingVias [All] p1: holewidth=11.81 width=23.62 viastyle="Through Hole" minholewidth=11.81 minwidth=23.62 maxholewidth=19.68 maxwidth=35.43
ShortCircuit ShortCircuit_1 [Net = 'No Net' vs Net = 'No Net'] p1: allowed=TRUE
ShortCircuit [All] p2: allowed=FALSE
SilkToSilkClearance SilkToSilkClearance_InvToFill [(ObjectKind = 'Text') And (TextKind <> 'Stroke Font') vs isFill] p1: silktosilkclearance=0
SilkToSilkClearance SilkToSilkClearance_InvLabels [(ObjectKind = 'Text') And (TextKind <> 'Stroke Font') vs (ObjectKind = 'Text') And (TextKind <> 'Stroke Font')] p2: silktosilkclearance=0
SilkToSilkClearance SilkToSilkClearance_Pb [(ObjectKind = 'Text') And (StringText = 'Pb') vs istrack and onsilkscreen] p3: silktosilkclearance=0
SilkToSilkClearance [All] p4: silktosilkclearance=5
SilkscreenOverComponentPads [All] p1: minsilkscreentomaskgap=2
SolderMaskExpansion SolderMaskExpansion_Vias [IsVia] p1: expansion=-25.59
SolderMaskExpansion [All] p2: expansion=1.5
Width [All] p1: maxlimit=98.43 minlimit=5 preferedwidth=5
15 further rules are at their usual default settings.

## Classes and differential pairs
component class U_DB32_Hardware_Kit: PCB1
component class U_FPGA: NT2 NT3 NT4 NT5 NT6 NT8 R1 R2 R3 R4 R7 R8 R12 R14 R18 R20 R22 R23 R24 R25 R26 R27 R28 U1
channel class SRAM_256Kx16_TSOP44: U_SRAM_K6R4016V1D-TC10T_256Kx161 U_SRAM_K6R4016V1D-TC10T_256Kx162
component class COM_SRAM: C15_CM C16_CM C17_CM C18_CM C19_CM C20_CM C21_CM C22_CM U4_CM U5_CM
component class COM_SDRAM: C7_CM C8_CM C9_CM C10_CM C11_CM C12_CM C13_CM C14_CM U2_CM U3_CM
component class U_CommonMemory_Termination: RN33 RN34 RN35 RN36 RN37 RN38
component class COM_FLASH: C1_CM C2_CM C3_CM C4_CM C5_CM C6_CM U1_CM
component class U_MOUNTS: "Altium Logo Bot1" "Altium Logo Top1" LB1 MH1 MH2 MH3
net class PLL: VCCA_PLL1 VCCA_PLL2 VCCA_PLL3 VCCA_PLL4
net class FPGACONF: CCLK DATA_DIN DONE FPGA_CCLK FPGA_DIN FPGA_DONE FPGA_INIT FPGA_M0 FPGA_M1 FPGA_M2 FPGA_PROGRAM FPGA_TCK FPGA_TDI FPGA_TDO FPGA_TMS INITN M0 M1 M2 PROGRAMN TCK TDI TDO TMS
component class U_FPGA_Power: C1_PL C2_PL C3_PL C4_PL C5_PL C6_PL C7_PL C8_PL C9_PL C10_PL C11_PL C12_PL C13_PL C14_PL C15_PL C16_PL L2_PL L3_PL L4_PL L5_PL R5
component class U_1WB_DS2406_EPROM: C1_ID C2_ID U1_ID
net class SRAM2_D[15..0]: SRAM2_D0 SRAM2_D1 SRAM2_D2 SRAM2_D3 SRAM2_D4 SRAM2_D5 SRAM2_D6 SRAM2_D7 SRAM2_D8 SRAM2_D9 SRAM2_D10 SRAM2_D11 SRAM2_D12 SRAM2_D13 SRAM2_D14 SRAM2_D15
net class SRAM2_A[18..0]: SRAM2_A0 SRAM2_A1 SRAM2_A2 SRAM2_A3 SRAM2_A4 SRAM2_A5 SRAM2_A6 SRAM2_A7 SRAM2_A8 SRAM2_A9 SRAM2_A10 SRAM2_A11 SRAM2_A12 SRAM2_A13 SRAM2_A14 SRAM2_A15 SRAM2_A16 SRAM2_A17 SRAM2_A18
net class SRAM1_D[15..0]: SRAM1_D0 SRAM1_D1 SRAM1_D2 SRAM1_D3 SRAM1_D4 SRAM1_D5 SRAM1_D6 SRAM1_D7 SRAM1_D8 SRAM1_D9 SRAM1_D10 SRAM1_D11 SRAM1_D12 SRAM1_D13 SRAM1_D14 SRAM1_D15
net class SRAM1_A[18..0]: SRAM1_A0 SRAM1_A1 SRAM1_A2 SRAM1_A3 SRAM1_A4 SRAM1_A5 SRAM1_A6 SRAM1_A7 SRAM1_A8 SRAM1_A9 SRAM1_A10 SRAM1_A11 SRAM1_A12 SRAM1_A13 SRAM1_A14 SRAM1_A15 SRAM1_A16 SRAM1_A17 SRAM1_A18
component class U_PSU: C23_CM C24_CM NT7 TP0 TP1 TP2 TP3 TP4
net class EXTEND_C[49..0]: EXTEND_C0 EXTEND_C1 EXTEND_C2 EXTEND_C3 EXTEND_C4 EXTEND_C5 EXTEND_C6 EXTEND_C7 EXTEND_C8 EXTEND_C9 EXTEND_C10 EXTEND_C11 EXTEND_C12 EXTEND_C13 EXTEND_C14 EXTEND_C15 EXTEND_C16 EXTEND_C17 EXTEND_C18 EXTEND_C19 EXTEND_C20 EXTEND_C21 EXTEND_C22 EXTEND_C23 EXTEND_C24 EXTEND_C25 EXTEND_C26 EXTEND_C27 EXTEND_C28 EXTEND_C29 EXTEND_C30 EXTEND_C31 EXTEND_C32 EXTEND_C33 EXTEND_C34 EXTEND_C35 EXTEND_C36 EXTEND_C37 EXTEND_C38 EXTEND_C39 EXTEND_C40 EXTEND_C41 EXTEND_C42 EXTEND_C43 EXTEND_C44 EXTEND_C45 EXTEND_C46 EXTEND_C47 EXTEND_C48 EXTEND_C49
net class EXTEND_B[49..0]: EXTEND_B0 EXTEND_B1 EXTEND_B2 EXTEND_B3 EXTEND_B4 EXTEND_B5 EXTEND_B6 EXTEND_B7 EXTEND_B8 EXTEND_B9 EXTEND_B10 EXTEND_B11 EXTEND_B12 EXTEND_B13 EXTEND_B14 EXTEND_B15 EXTEND_B16 EXTEND_B17 EXTEND_B18 EXTEND_B19 EXTEND_B20 EXTEND_B21 EXTEND_B22 EXTEND_B23 EXTEND_B24 EXTEND_B25 EXTEND_B26 EXTEND_B27 EXTEND_B28 EXTEND_B29 EXTEND_B30 EXTEND_B31 EXTEND_B32 EXTEND_B33 EXTEND_B34 EXTEND_B35 EXTEND_B36 EXTEND_B37 EXTEND_B38 EXTEND_B39 EXTEND_B40 EXTEND_B41 EXTEND_B42 EXTEND_B43 EXTEND_B44 EXTEND_B45 EXTEND_B46 EXTEND_B47 EXTEND_B48 EXTEND_B49
net class EXTEND_A[49..0]: EXTEND_A0 EXTEND_A1 EXTEND_A2 EXTEND_A3 EXTEND_A4 EXTEND_A5 EXTEND_A6 EXTEND_A7 EXTEND_A8 EXTEND_A9 EXTEND_A10 EXTEND_A11 EXTEND_A12 EXTEND_A13 EXTEND_A14 EXTEND_A15 EXTEND_A16 EXTEND_A17 EXTEND_A18 EXTEND_A19 EXTEND_A20 EXTEND_A21 EXTEND_A22 EXTEND_A23 EXTEND_A24 EXTEND_A25 EXTEND_A26 EXTEND_A27 EXTEND_A28 EXTEND_A29 EXTEND_A30 EXTEND_A31 EXTEND_A32 EXTEND_A33 EXTEND_A34 EXTEND_A35 EXTEND_A36 EXTEND_A37 EXTEND_A38 EXTEND_A39 EXTEND_A40 EXTEND_A41 EXTEND_A42 EXTEND_A43 EXTEND_A44 EXTEND_A45 EXTEND_A46 EXTEND_A47 EXTEND_A48 EXTEND_A49
net class DAU_TFT_RED[4..0]: DAU_TFT_RED0 DAU_TFT_RED1 DAU_TFT_RED2 DAU_TFT_RED3 DAU_TFT_RED4
net class DAU_TFT_GREEN[5..0]: DAU_TFT_GREEN0 DAU_TFT_GREEN1 DAU_TFT_GREEN2 DAU_TFT_GREEN3 DAU_TFT_GREEN4 DAU_TFT_GREEN5
net class DAU_TFT_CL[3..1]: DAU_TFT_CL1 DAU_TFT_CL2 DAU_TFT_CL3
net class DAU_TFT_BLUE[4..0]: DAU_TFT_BLUE0 DAU_TFT_BLUE1 DAU_TFT_BLUE2 DAU_TFT_BLUE3 DAU_TFT_BLUE4
net class BUS_A[24..1]: BUS_A1 BUS_A2 BUS_A3 BUS_A4 BUS_A5 BUS_A6 BUS_A7 BUS_A8 BUS_A9 BUS_A10 BUS_A11 BUS_A12 BUS_A13 BUS_A14 BUS_A15 BUS_A16 BUS_A17 BUS_A18 BUS_A19 BUS_A20 BUS_A21 BUS_A22 BUS_A23 BUS_A24
component class U_Bypass_Board: C1_MB C1_PSU C2_MB C4_MB C6_MB
component class U_Bypass_3V3: C38_FP C39_FP C40_FP C41_FP C42_FP C43_FP C44_FP C45_FP C46_FP C47_FP C48_FP C49_FP C50_FP C51_FP C52_FP C53_FP C54_FP C55_FP C56_FP C57_FP C58_FP C59_FP C60_FP C61_FP C62_FP C63_FP C64_FP C65_FP C66_FP C67_FP C68_FP C69_FP C70_FP C71_FP C72_FP C73_FP C74_FP C75_FP C76_FP C77_FP C78_FP C79_FP C80_FP C81_FP C82_FP C83_FP C84_FP C85_FP C86_FP C87_FP C88_FP C89_FP C90_FP C91_FP C92_FP C93_FP C94_FP C95_FP C96_FP C97_FP C98_FP C99_FP C100_FP C101_FP C102_FP C103_FP C104_FP C105_FP C106_FP
component class U_Bypass_1V2: C1_FP C2_FP C3_FP C4_FP C5_FP C5_MB C6_FP C7_FP C8_FP C9_FP C10_FP C11_FP C12_FP C15_FP C16_FP C17_FP C18_FP C19_FP C20_FP C21_FP C22_FP C23_FP C24_FP C25_FP C29_FP
component class U_MotherBoardConnectors: HDR_B HDR_L HDR_T NT1
net class BUS_D[31..0]: BUS_D0 BUS_D1 BUS_D2 BUS_D3 BUS_D4 BUS_D5 BUS_D6 BUS_D7 BUS_D8 BUS_D9 BUS_D10 BUS_D11 BUS_D12 BUS_D13 BUS_D14 BUS_D15 BUS_D16 BUS_D17 BUS_D18 BUS_D19 BUS_D20 BUS_D21 BUS_D22 BUS_D23 BUS_D24 BUS_D25 BUS_D26 BUS_D27 BUS_D28 BUS_D29 BUS_D30 BUS_D31
net class BUS_NBE[3..0]: BUS_NBE0 BUS_NBE1 BUS_NBE2 BUS_NBE3
net class DIP[7..0]: DIP0 DIP1 DIP2 DIP3 DIP4 DIP5 DIP6 DIP7
net class FPGA_ID[3..0]: FPGA_ID0 FPGA_ID1 FPGA_ID2 FPGA_ID3
net class FPGA_M[2..0]: FPGA_M0 FPGA_M1 FPGA_M2
net class IO[35..0]: IO0 IO1 IO2 IO3 IO4 IO5 IO6 IO7 IO8 IO9 IO10 IO11 IO12 IO13 IO14 IO15 IO16 IO17 IO18 IO19 IO20 IO21 IO22 IO23 IO24 IO25 IO26 IO27 IO28 IO29 IO30 IO31 IO32 IO33 IO34 IO35
net class LED[7..0]: LED0 LED1 LED2 LED3 LED4 LED5 LED6 LED7
net class SW[4..0]: SW0 SW1 SW2 SW3 SW4
differential pair class DIFF_IN: DIFF_RX0 DIFF_RX1 DIFF_RX2 DIFF_RX3
differential pair class DIFF_OUT: DIFF_TX0 DIFF_TX1 DIFF_TX2 DIFF_TX3
net class PWRNET: 1V2 3V3 5V0 AGND GND
net class CLKS: BUS_SDRAM_FEEDBACK FPGA_CLK FPGA_CLK1 REF_CLK UGCLK0 UGCLK1 UGCLK2
component class U_DaughterBoard_LEDS: C98 LED1 LED2 R19 R21 U9
component class U_SRAM_K6R4016V1D-TC10T_256Kx161: C1_SMA C2_SMA C3_SMA C4_SMA U1_SMA
component class U_SRAM_K6R4016V1D-TC10T_256Kx162: C1_SM C1_SMB C2_SM C2_SMB C3_SMB C4_SM C4_SMB U1_SM U1_SMB
component class U_PSU_MAX1831_1V2_ALT: C15 C16 C17 C18 C19 C20 C21 C22 L1_PS R11 R13 R15 R16 R17 TP7 TP8 U2

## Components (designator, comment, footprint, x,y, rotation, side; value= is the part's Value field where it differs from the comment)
"Altium Logo Bot1" "Altium" Logo-Altium 2177.17,129.92 r180 bottom
"Altium Logo Top1" "Altium" Logo-Altium 1051.18,129.92 r0 top
C1_CM "10nF 16V" CAPC1005-STAR 2185.04,2969.49 r270 bottom (schematic designator C3)
C1_FP "10uF 10V" CAPC2012-STAR 889.76,1551.18 r90 bottom
C1_ID "0.1uF 16V" CAPC1005-STAR 2807.08,3015.74 r180 bottom (schematic designator C1)
C1_MB "220uF 10V" CAPC7343-STAR 681.1,1255.9 r270 bottom
C1_PL "2.2uF 10V" CAPC1608-STAR 1429.13,909.45 r0 bottom
C1_SMA "0.1uF 16V" CAPC1005-STAR 2915.44,1059.04 r90 top (schematic designator C1_SM)
C1_SMB "0.1uF 16V" CAPC1005-STAR 2391.82,980.3 r270 bottom (schematic designator C1_SM)
C2_CM "10nF 16V" CAPC1005-STAR 2370.07,2842.51 r180 bottom (schematic designator C4)
C2_FP "10uF 10V" CAPC2012-STAR 1606.3,791.34 r0 bottom
C2_ID "10nF 16V" CAPC1005-STAR 2807.08,2968.5 r0 bottom (schematic designator C2)
C2_MB "220uF 10V" CAPC7343-STAR 1870.07,2862.2 r180 bottom
C2_PL "0.1uF 16V" CAPC1005-STAR 1342.52,874.01 r270 bottom
C2_SMA "0.1uF 16V" CAPC1005-STAR 2309.14,1055.11 r270 top (schematic designator C2_SM)
C2_SMB "0.1uF 16V" CAPC1005-STAR 3007.87,1133.86 r90 bottom (schematic designator C2_SM)
C3_CM "10nF 16V" CAPC1005-STAR 2263.78,3186.02 r180 bottom (schematic designator C5)
C3_FP "10uF 10V" CAPC2012-STAR 2153.54,1551.18 r90 bottom
C3_PL "10nF 16V" CAPC1005-STAR 1279.52,874.01 r270 bottom
C3_SMA "10nF 16V" CAPC1005-STAR 2915.44,980.3 r270 top (schematic designator C3_SM)
C3_SMB "10nF 16V" CAPC1005-STAR 2391.82,1062.98 r90 bottom (schematic designator C3_SM)
C4_CM "0.1uF 16V" CAPC1005-STAR 2141.73,2969.49 r270 bottom (schematic designator C6)
C4_FP "0.1uF 16V" CAPC1005-STAR 1303.15,1240.16 r180 bottom
C4_PL "1nF 50V" CAPC1005-STAR 1216.53,874.01 r270 bottom
C4_SMA "10nF 16V" CAPC1005-STAR 2259.84,1055.12 r270 top (schematic designator C4_SM)
C4_SMB "10nF 16V" CAPC1005-STAR 3007.87,1055.12 r270 bottom (schematic designator C4_SM)
C5_CM "0.1uF 16V" CAPC1005-STAR 2370.07,2799.21 r180 bottom (schematic designator C1)
C5_FP "0.1uF 16V" CAPC1005-STAR 1444.88,1255.9 r90 bottom
C5_MB "220uF 10V" CAPC7343-STAR 2492.13,1551.18 r0 bottom
C5_PL "2.2uF 10V" CAPC1608-STAR 1669.29,2035.43 r180 bottom
C6_CM "0.1uF 16V" CAPC1005-STAR 2263.78,3233.27 r180 bottom (schematic designator C2)
C6_FP "0.1uF 16V" CAPC1005-STAR 1602.36,1255.9 r90 bottom
C6_PL "0.1uF 16V" CAPC1005-STAR 1751.97,2062.99 r90 bottom
C7_CM "10nF 16V" CAPC1005-STAR 1440.94,3980.31 r180 top (schematic designator C5)
C7_FP "0.1uF 16V" CAPC1005-STAR 1744.09,1240.16 r0 bottom
C7_PL "10nF 16V" CAPC1005-STAR 1814.96,2062.99 r90 bottom
C8_CM "10nF 16V" CAPC1005-STAR 1629.92,3980.31 r180 top (schematic designator C6)
C8_FP "0.1uF 16V" CAPC1005-STAR 1759.84,1417.32 r90 bottom
C8_PL "1nF 50V" CAPC1005-STAR 1877.95,2062.99 r90 bottom
C9_CM "0.1uF 16V" CAPC1005-STAR 2149.6,4007.87 r270 top (schematic designator C1)
C9_FP "0.1uF 16V" CAPC1005-STAR 1759.84,1535.43 r270 bottom
C9_PL "2.2uF 10V" CAPC1608-STAR 1381.89,2035.43 r0 bottom
C10_CM "0.1uF 16V" CAPC1005-STAR 1535.43,3374.01 r180 top (schematic designator C2)
C10_FP "0.1uF 16V" CAPC1005-STAR 1681.1,1696.85 r270 bottom
C10_PL "0.1uF 16V" CAPC1005-STAR 1303.15,2059.05 r90 bottom
C11_CM "10nF 16V" CAPC1005-STAR 2039.37,3374.01 r180 bottom (schematic designator C7)
C11_FP "0.1uF 16V" CAPC1005-STAR 1523.62,1696.85 r270 bottom
C11_PL "10nF 16V" CAPC1005-STAR 1240.15,2059.05 r90 bottom
C12_CM "10nF 16V" CAPC1005-STAR 1850.39,3374.01 r180 bottom (schematic designator C8)
C12_FP "0.1uF 16V" CAPC1005-STAR 1366.14,1696.85 r270 bottom
C12_PL "1nF 50V" CAPC1005-STAR 1177.16,2059.05 r90 bottom
C13_CM "0.1uF 16V" CAPC1005-STAR 1279.52,3405.5 r180 bottom (schematic designator C3)
C13_PL "2.2uF 10V" CAPC1608-STAR 1700.78,885.83 r270 bottom
C14_CM "0.1uF 16V" CAPC1005-STAR 1803.15,3999.99 r90 bottom (schematic designator C4)
C14_PL "0.1uF 16V" CAPC1005-STAR 1751.97,889.76 r270 bottom
C15 "22uF 10V" CAPC3225-STAR 2637.79,1976.37 r180 top (schematic designator C1_PS)
C15_CM "0.1uF 16V" CAPC1005-STAR 2604.05,3326.76 r0 top (schematic designator C1)
C15_FP "10nF 16V" CAPC1005-STAR 1287.4,1417.32 r90 bottom
C15_PL "10nF 16V" CAPC1005-STAR 1814.96,889.76 r270 bottom
C16 "470pF 50V" CAPC1005-STAR 2944.88,1740.15 r90 top (schematic designator C2_PS)
C16_CM "0.1uF 16V" CAPC1005-STAR 2602.36,4027.55 r180 top (schematic designator C2)
C16_FP "10nF 16V" CAPC1005-STAR 1366.14,1255.9 r90 bottom
C16_PL "1nF 50V" CAPC1005-STAR 1877.95,889.76 r270 bottom
C17 "220uF 10V" CAPC7343-STAR 2814.95,2149.6 r180 top (schematic designator C3_PS)
C17_CM "10nF 16V" CAPC1005-STAR 2604.05,3370.07 r0 top (schematic designator C5)
C17_FP "10nF 16V" CAPC1005-STAR 1523.62,1255.9 r90 bottom
C18 "2.2uF 10V" CAPC1608-STAR 2456.69,1692.91 r180 top (schematic designator C4_PS)
C18_CM "10nF 16V" CAPC1005-STAR 2602.08,3984.25 r180 top (schematic designator C6)
C18_FP "10nF 16V" CAPC1005-STAR 1681.1,1255.9 r90 bottom
C19 "10uF 10V" CAPC2012-STAR 2988.18,1425.19 r270 top (schematic designator C5_PS)
C19_CM "0.1uF 16V" CAPC1005-STAR 2602.36,3330.7 r0 bottom (schematic designator C3)
C19_FP "10nF 16V" CAPC1005-STAR 1303.15,1712.59 r180 bottom
C20 "22uF 10V" CAPC3225-STAR 2748.03,1503.93 r180 top (schematic designator C6_PS)
C20_CM "0.1uF 16V" CAPC1005-STAR 2665.35,4027.55 r0 bottom (schematic designator C4)
C20_FP "10nF 16V" CAPC1005-STAR 1779.52,1476.37 r180 bottom
C21 "1uF 25V" CAPC3216-STAR 2448.81,1783.46 r0 top (schematic designator C7_PS)
C21_CM "10nF 16V" CAPC1005-STAR 2602.36,3370.07 r0 bottom (schematic designator C7)
C21_FP "10nF 16V" CAPC1005-STAR 1744.09,1712.6 r0 bottom
C22 "10uF 10V" CAPC2012-STAR 3118.1,1795.27 r270 top (schematic designator C8_PS)
C22_CM "10nF 16V" CAPC1005-STAR 2665.35,3984.25 r0 bottom (schematic designator C8)
C22_FP "10nF 16V" CAPC1005-STAR 1602.36,1696.85 r270 bottom
C23_CM "10uF 10V" CAPC2012-STAR 2765.75,3087.59 r0 bottom
C23_FP "10nF 16V" CAPC1005-STAR 1444.88,1696.85 r270 bottom
C24_CM "10uF 10V" CAPC2012-STAR 2216.53,3986.21 r270 bottom
C24_FP "10nF 16V" CAPC1005-STAR 1267.71,1476.37 r0 bottom
C25_FP "10nF 16V" CAPC1005-STAR 1287.4,1535.43 r90 bottom
C38_FP "10uF 10V" CAPC2012-STAR 1236.22,2153.54 r0 bottom
C39_FP "10uF 10V" CAPC2012-STAR 889.76,1716.53 r270 bottom
C40_FP "10uF 10V" CAPC2012-STAR 1826.89,2152.54 r180 bottom
C41_FP "10uF 10V" CAPC2012-STAR 889.76,1188.97 r90 bottom
C42_FP "10uF 10V" CAPC2012-STAR 2153.54,1708.66 r270 bottom
C43_FP "10uF 10V" CAPC2012-STAR 2157.48,1185.04 r90 bottom
C44_FP "10uF 10V" CAPC2012-STAR 1795.27,791.34 r180 bottom
C45_FP "10uF 10V" CAPC2012-STAR 1248.03,791.34 r0 bottom
C46_FP "0.1uF 16V" CAPC1005-STAR 1563.67,1340.97 r90 bottom
C47_FP "0.1uF 16V" CAPC1005-STAR 1445.56,1340.97 r90 bottom
C48_FP "0.1uF 16V" CAPC1005-STAR 1658.54,1437.01 r180 bottom
C49_FP "0.1uF 16V" CAPC1005-STAR 1658.46,1515.75 r180 bottom
C50_FP "0.1uF 16V" CAPC1005-STAR 1562.99,1610.23 r270 bottom
C51_FP "0.1uF 16V" CAPC1005-STAR 1603.04,1340.97 r90 bottom
C52_FP "0.1uF 16V" CAPC1005-STAR 1523.62,1610.23 r270 bottom
C53_FP "0.1uF 16V" CAPC1005-STAR 1658.46,1476.38 r180 bottom
C54_FP "0.1uF 16V" CAPC1005-STAR 1388.78,1555.12 r0 bottom
C55_FP "0.1uF 16V" CAPC1005-STAR 1444.88,1610.23 r270 bottom
C56_FP "0.1uF 16V" CAPC1005-STAR 1658.46,1555.12 r180 bottom
C62_FP "10nF 16V" CAPC1005-STAR 1602.36,1610.23 r270 bottom
C63_FP "10nF 16V" CAPC1005-STAR 1682.09,1340.55 r90 bottom
C64_FP "10nF 16V" CAPC1005-STAR 1641.73,1610.23 r270 bottom
C65_FP "10nF 16V" CAPC1005-STAR 1389.76,1397.63 r0 bottom
C66_FP "10nF 16V" CAPC1005-STAR 1389.76,1437 r0 bottom
C67_FP "10nF 16V" CAPC1005-STAR 1405.51,1610.23 r270 bottom
C68_FP "10nF 16V" CAPC1005-STAR 1388.78,1515.75 r0 bottom
C69_FP "10nF 16V" CAPC1005-STAR 1366.14,1610.23 r270 bottom
C70_FP "10nF 16V" CAPC1005-STAR 1642.41,1340.97 r90 bottom
C71_FP "10nF 16V" CAPC1005-STAR 1484.25,1610.23 r270 bottom
C72_FP "10nF 16V" CAPC1005-STAR 1484.93,1340.89 r90 bottom
C73_FP "10nF 16V" CAPC1005-STAR 1366.82,1340.89 r90 bottom
C74_FP "10nF 16V" CAPC1005-STAR 1406.19,1340.97 r90 bottom
C75_FP "10nF 16V" CAPC1005-STAR 1389.76,1476.37 r0 bottom
C76_FP "10nF 16V" CAPC1005-STAR 1658.46,1397.64 r180 bottom
C77_FP "10nF 16V" CAPC1005-STAR 1524.3,1340.89 r90 bottom
C78_FP "10nF 16V" CAPC1005-STAR 2248.03,2141.73 r90 bottom
C79_FP "10nF 16V" CAPC1005-STAR 1940.94,2141.73 r270 bottom
C80_FP "10nF 16V" CAPC1005-STAR 1114.17,2070.86 r90 bottom
C81_FP "10nF 16V" CAPC1005-STAR 1114.17,2153.54 r270 bottom
C82_FP "10nF 16V" CAPC1005-STAR 866.14,1854.33 r90 bottom
C83_FP "10nF 16V" CAPC1005-STAR 913.38,1854.33 r90 bottom
C84_FP "10nF 16V" CAPC1005-STAR 913.38,1055.12 r270 bottom
C85_FP "10nF 16V" CAPC1005-STAR 866.14,1055.12 r270 bottom
C86_FP "10nF 16V" CAPC1005-STAR 1106.3,767.71 r180 bottom
C87_FP "10nF 16V" CAPC1005-STAR 1106.3,814.96 r180 bottom
C88_FP "10nF 16V" CAPC1005-STAR 1937,779.53 r0 bottom
C89_FP "10nF 16V" CAPC1005-STAR 1937,826.77 r0 bottom
C90_FP "10nF 16V" CAPC1005-STAR 2181.1,1047.24 r270 bottom
C91_FP "10nF 16V" CAPC1005-STAR 2133.85,1047.24 r270 bottom
C92_FP "10nF 16V" CAPC1005-STAR 2173.22,1842.52 r90 bottom
C93_FP "10nF 16V" CAPC1005-STAR 2125.98,1842.52 r90 bottom
C98 "0.1uF 16V" CAPC1005-STAR 1259.84,236.22 r0 bottom (schematic designator C1_SL)
HDR_B "MOLEX - 54075-1009" 54075 1893.7,472.44 r0 bottom locked
HDR_L "MOLEX - 54075-1009" 54075 307.09,1472.44 r270 bottom locked
HDR_T "MOLEX - 54075-1009" 54075 1893.7,2472.44 r0 bottom locked
L1_PS "2u2, 15A, 4R2, SMD" IND-EPCOS-SMD-B82559 2944.88,1649.6 r90 bottom locked
L2_PL "1K at 100MHz 300mA" INDC2012-STAR 1437.01,838.58 r180 bottom
L3_PL "1K at 100MHz 300mA" INDC2012-STAR 1625.98,2106.29 r0 bottom
L4_PL "1K at 100MHz 300mA" INDC2012-STAR 1409.45,2106.29 r180 bottom
L5_PL "1K at 100MHz 300mA" INDC2012-STAR 1606.3,893.7 r0 bottom
LED1 "RED" LED2012-STAR 1974.41,169.29 r180 top (schematic designator LED1_SL)
LED2 "GREEN" LED2012-STAR 1261.81,169.29 r180 top (schematic designator LED2_SL)
MH1 "MOUNTING HOLE 3MM" MOUNTING_HOLE_3MM 1618.11,129.92 r180 top locked
MH2 "MOUNTING HOLE 3MM" MOUNTING_HOLE_3MM 129.92,4326.77 r180 top locked
MH3 "MOUNTING HOLE 3MM" MOUNTING_HOLE_3MM 3106.3,4326.77 r180 top locked
NT1 "Net Tie SMT2" NETTIE-SMT2-8X8 1625.75,2700.42 r90 bottom net-tie
NT2 "Net Tie SMT2" NETTIE-SMT2-8X8 1752.2,2680.73 r90 bottom net-tie
NT3 "Net Tie SMT2" NETTIE-SMT2-8X8 1720.7,2680.73 r90 bottom net-tie
NT4 "Net Tie SMT2" NETTIE-SMT2-8X8 1689.21,2680.73 r90 bottom net-tie
NT5 "Net Tie SMT2" NETTIE-SMT2-8X8 1657.71,2680.73 r90 bottom net-tie
NT6 "Net Tie SMT2" NETTIE-SMT2-8X8 1464.21,256.87 r0 bottom net-tie
NT7 "Net Tie SMT2" NETTIE-SMT2-8X8 2519.44,1987.83 r90 top net-tie
NT8 "Net Tie SMT2" NETTIE-SMT2-8X8 1562.76,2165 r90 top net-tie
PBFREE "" LEAD_FREE_S 292.32,3631.89 r180 bottom
R1 "4K7 1%" RESC1005-STAR 1984.25,2141.73 r90 bottom
R2 "4K7 1%" RESC1005-STAR 964.56,2153.53 r270 bottom
R3 "4K7 1%" RESC1005-STAR 2114.17,2141.73 r90 bottom
R4 "4K7 1%" RESC1005-STAR 2200.78,2141.73 r270 bottom
R5 "10K 1%" RESC1005-STAR 1066.93,2153.54 r90 bottom
R7 "4K7 1%" RESC1005-STAR 2070.86,2141.73 r90 bottom
R8 "100R 1%" RESC1005-STAR 2114.17,2035.43 r270 bottom
R11 "2K7 1%" RESC1005-STAR 2787.4,1866.14 r0 top (schematic designator R1_PS)
R12 "100R 1%" RESC1005-STAR 913.38,2153.54 r270 bottom
R13 "10R 1%" RESC1005-STAR 2492.12,1622.04 r90 top (schematic designator R2_PS)
R14 "100R 1%" RESC1005-STAR 862.2,2153.54 r270 bottom
R15 "27K 1%" RESC1005-STAR 2889.76,1866.14 r0 top (schematic designator R3_PS)
R16 "2K7 1%" RESC1005-STAR 2992.12,1866.14 r0 top (schematic designator R4_PS)
R17 "100K 1%" RESC1005-STAR 2992.12,1814.96 r0 top (schematic designator R5_PS)
R18 "100R 1%" RESC1005-STAR 1940.94,2035.43 r270 bottom
R19 "270R 1%" RESC1005-STAR 1974.41,169.29 r180 bottom (schematic designator R1_SL)
R20 "100R 1%" RESC1005-STAR 811.02,2153.54 r270 bottom
R21 "270R 1%" RESC1005-STAR 1248.03,169.29 r180 bottom (schematic designator R2_SL)
R22 "100R 1%" RESC1005-STAR 1015.75,2153.54 r270 bottom
R23 "100R 1%" RESC1005-STAR 2027.55,2141.73 r270 bottom
R24 "100R 1%" RESC1005-STAR 1984.25,2035.43 r270 bottom
R25 "100R 1%" RESC1005-STAR 2157.48,2141.73 r270 bottom
R26 "100R 1%" RESC1005-STAR 2070.86,2035.43 r270 bottom
R27 "100R 1%" RESC1005-STAR 2157.48,2035.43 r270 bottom
R28 "100R 1%" RESC1005-STAR 2027.55,2035.43 r270 bottom
RN33 "RESNET 4 x 100R" RESNET-1005X4 1662.99,3301.18 r90 bottom
RN34 "RESNET 4 x 100R" RESNET-1005X4 1804.73,3301.18 r270 bottom
RN35 "RESNET 4 x 100R" RESNET-1005X4 1366.74,3301.18 r90 bottom
RN36 "RESNET 4 x 100R" RESNET-1005X4 1508.47,3301.18 r270 bottom
RN37 "RESNET 4 x 100R" RESNET-1005X4 1559.66,4025.59 r90 bottom
RN38 "RESNET 4 x 100R" RESNET-1005X4 1701.39,4025.59 r270 bottom
TP0 "GND" TestPin 2875.71,3138.67 r0 top
TP1 "3V3" TestPin 2875.71,3038.67 r0 top
TP2 "GND" TestPin 2875.71,2938.66 r0 top
TP3 "5V0" TestPin 2875.71,2838.67 r0 top
TP4 "1V2" TestPin 2875.71,2738.67 r0 top
U1 "LFECP33E-3FN672C" BGA100P26X26-672 1523.62,1476.38 r0 top locked
U1_CM "S29GL256N11FFIV10" BGA100P8X8-64 2370.08,3036.42 r180 top locked (schematic designator U1)
U1_ID "DS2406" TSOC6 2712.59,2846.45 r90 bottom (schematic designator U1)
U1_SMA "SRAM-256Kx16" TSOP80P1176-44 2612.28,1059.06 r90 top locked (schematic designator U1_SM)
U1_SMB "SRAM-256Kx16" TSOP80P1176-44 2702.83,1059.06 r90 bottom locked (schematic designator U1_SM)
U2 "MAX1831EEE" SOP63P602-16 2708.58,1720.75 r180 top locked (schematic designator U1_PS)
U2_CM "SDRAM-16Mx16" TSOP80P1176-54 1740.16,3677.17 r0 top locked (schematic designator U1)
U3_CM "SDRAM-16Mx16" TSOP80P1176-54 1740.16,3677.17 r180 bottom locked (schematic designator U2)
U4_CM "SRAM-256Kx16" TSOP80P1176-44 2602.36,3677.17 r0 top locked (schematic designator U1)
U5_CM "SRAM-256Kx16" TSOP80P1176-44 2665.35,3677.17 r180 bottom locked (schematic designator U2)
U9 "SN74LVC1G04DBV" SOT95P280-5 1397.64,165.35 r0 bottom (schematic designator U1_SL)

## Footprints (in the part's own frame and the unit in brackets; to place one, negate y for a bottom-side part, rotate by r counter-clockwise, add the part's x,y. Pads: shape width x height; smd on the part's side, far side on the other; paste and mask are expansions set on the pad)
54075 [mm]
  rect 0.5x1.9 smd: 1(-19.6,3.4) 2(-19.6,-3.4) 3(-18.8,3.4) 4(-18.8,-3.4) 5(-18,3.4) 6(-18,-3.4) 7(-17.2,3.4) 8(-17.2,-3.4) 9(-16.4,3.4) 10(-16.4,-3.4) 11(-15.6,3.4) 12(-15.6,-3.4) 13(-14.8,3.4) 14(-14.8,-3.4) 15(-14,3.4) 16(-14,-3.4) 17(-13.2,3.4) 18(-13.2,-3.4) 19(-12.4,3.4) 20(-12.4,-3.4) 21(-11.6,3.4) 22(-11.6,-3.4) 23(-10.8,3.4) 24(-10.8,-3.4) 25(-10,3.4) 26(-10,-3.4) 27(-9.2,3.4) 28(-9.2,-3.4) 29(-8.4,3.4) 30(-8.4,-3.4) 31(-7.6,3.4) 32(-7.6,-3.4) 33(-6.8,3.4) 34(-6.8,-3.4) 35(-6,3.4) 36(-6,-3.4) 37(-5.2,3.4) 38(-5.2,-3.4) 39(-4.4,3.4) 40(-4.4,-3.4) 41(-3.6,3.4) 42(-3.6,-3.4) 43(-2.8,3.4) 44(-2.8,-3.4) 45(-2,3.4) 46(-2,-3.4) 47(-1.2,3.4) 48(-1.2,-3.4) 49(-0.4,3.4) 50(-0.4,-3.4) 51(0.4,3.4) 52(0.4,-3.4) 53(1.2,3.4) 54(1.2,-3.4) 55(2,3.4) 56(2,-3.4) 57(2.8,3.4) 58(2.8,-3.4) 59(3.6,3.4) 60(3.6,-3.4) 61(4.4,3.4) 62(4.4,-3.4) 63(5.2,3.4) 64(5.2,-3.4) 65(6,3.4) 66(6,-3.4) 67(6.8,3.4) 68(6.8,-3.4) 69(7.6,3.4) 70(7.6,-3.4) 71(8.4,3.4) 72(8.4,-3.4) 73(9.2,3.4) 74(9.2,-3.4) 75(10,3.4) 76(10,-3.4) 77(10.8,3.4) 78(10.8,-3.4) 79(11.6,3.4) 80(11.6,-3.4) 81(12.4,3.4) 82(12.4,-3.4) 83(13.2,3.4) 84(13.2,-3.4) 85(14,3.4) 86(14,-3.4) 87(14.8,3.4) 88(14.8,-3.4) 89(15.6,3.4) 90(15.6,-3.4) 91(16.4,3.4) 92(16.4,-3.4) 93(17.2,3.4) 94(17.2,-3.4) 95(18,3.4) 96(18,-3.4) 97(18.8,3.4) 98(18.8,-3.4) 99(19.6,3.4) 100(19.6,-3.4)
  round 1.6 hole 0.7: MH1(-26.7,4.2) MH2(-25.9,-4.2) MH3(26.7,4.2) MH4(25.9,-4.2)
  round 4.8 hole 5.1 unplated: MH5(-26.3,0) MH6(26.3,0)
  Top Layer keep-out region: -20.15,2.15 20.15,2.15 20.15,-2.15 -20.15,-2.15
  silkscreen extent -30.35,-4.4 30.35,5.02, body extent -30.36,-4.42 30.34,4.38, height 3.75
BGA100P8X8-64 [mm] "AMD 64-Ball Fortfied Ball grid Array (FBGA)"
  round 0.5 smd: A1(-3.5,-3.5) A2(-3.5,-2.5) A3(-3.5,-1.5) A4(-3.5,-0.5) A5(-3.5,0.5) A6(-3.5,1.5) A7(-3.5,2.5) A8(-3.5,3.5) B1(-2.5,-3.5) B2(-2.5,-2.5) B3(-2.5,-1.5) B4(-2.5,-0.5) B5(-2.5,0.5) B6(-2.5,1.5) B7(-2.5,2.5) B8(-2.5,3.5) C1(-1.5,-3.5) C2(-1.5,-2.5) C3(-1.5,-1.5) C4(-1.5,-0.5) C5(-1.5,0.5) C6(-1.5,1.5) C7(-1.5,2.5) C8(-1.5,3.5) D1(-0.5,-3.5) D2(-0.5,-2.5) D3(-0.5,-1.5) D4(-0.5,-0.5) D5(-0.5,0.5) D6(-0.5,1.5) D7(-0.5,2.5) D8(-0.5,3.5) E1(0.5,-3.5) E2(0.5,-2.5) E3(0.5,-1.5) E4(0.5,-0.5) E5(0.5,0.5) E6(0.5,1.5) E7(0.5,2.5) E8(0.5,3.5) F1(1.5,-3.5) F2(1.5,-2.5) F3(1.5,-1.5) F4(1.5,-0.5) F5(1.5,0.5) F6(1.5,1.5) F7(1.5,2.5) F8(1.5,3.5) G1(2.5,-3.5) G2(2.5,-2.5) G3(2.5,-1.5) G4(2.5,-0.5) G5(2.5,0.5) G6(2.5,1.5) G7(2.5,2.5) G8(2.5,3.5) H1(3.5,-3.5) H2(3.5,-2.5) H3(3.5,-1.5) H4(3.5,-0.5) H5(3.5,0.5) H6(3.5,1.5) H7(3.5,2.5) H8(3.5,3.5)
  silkscreen extent -6.5,-6.32 6.5,5.5, body extent -6.35,-5.41 6.41,5.36, height 1
BGA100P26X26-672 [mm] "672-Ball FineLine Ball Grid Array (FBGA672)"
  round 0.5 smd: A2(-11.5,12.5) A3(-10.5,12.5) A4(-9.5,12.5) A5(-8.5,12.5) A6(-7.5,12.5) A7(-6.5,12.5) A8(-5.5,12.5) A9(-4.5,12.5) A10(-3.5,12.5) A11(-2.5,12.5) A12(-1.5,12.5) A13(-0.5,12.5) A14(0.5,12.5) A15(1.5,12.5) A16(2.5,12.5) A17(3.5,12.5) A18(4.5,12.5) A19(5.5,12.5) A20(6.5,12.5) A21(7.5,12.5) A22(8.5,12.5) A23(9.5,12.5) A24(10.5,12.5) A25(11.5,12.5) AA1(-12.5,-7.5) AA2(-11.5,-7.5) AA3(-10.5,-7.5) AA4(-9.5,-7.5) AA5(-8.5,-7.5) AA6(-7.5,-7.5) AA7(-6.5,-7.5) AA8(-5.5,-7.5) AA9(-4.5,-7.5) AA10(-3.5,-7.5) AA11(-2.5,-7.5) AA12(-1.5,-7.5) AA13(-0.5,-7.5) AA14(0.5,-7.5) AA15(1.5,-7.5) AA16(2.5,-7.5) AA17(3.5,-7.5) AA18(4.5,-7.5) AA19(5.5,-7.5) AA20(6.5,-7.5) AA21(7.5,-7.5) AA22(8.5,-7.5) AA23(9.5,-7.5) AA24(10.5,-7.5) AA25(11.5,-7.5) AA26(12.5,-7.5) AB1(-12.5,-8.5) AB2(-11.5,-8.5) AB3(-10.5,-8.5) AB4(-9.5,-8.5) AB5(-8.5,-8.5) AB6(-7.5,-8.5) AB7(-6.5,-8.5) AB8(-5.5,-8.5) AB9(-4.5,-8.5) AB10(-3.5,-8.5) AB11(-2.5,-8.5) AB12(-1.5,-8.5) AB13(-0.5,-8.5) AB14(0.5,-8.5) AB15(1.5,-8.5) AB16(2.5,-8.5) AB17(3.5,-8.5) AB18(4.5,-8.5) AB19(5.5,-8.5) AB20(6.5,-8.5) AB21(7.5,-8.5) AB22(8.5,-8.5) AB23(9.5,-8.5) AB24(10.5,-8.5) AB25(11.5,-8.5) AB26(12.5,-8.5) AC1(-12.5,-9.5) AC2(-11.5,-9.5) AC3(-10.5,-9.5) AC4(-9.5,-9.5) AC5(-8.5,-9.5) AC6(-7.5,-9.5) AC7(-6.5,-9.5) AC8(-5.5,-9.5) AC9(-4.5,-9.5) AC10(-3.5,-9.5) AC11(-2.5,-9.5) AC12(-1.5,-9.5) AC13(-0.5,-9.5) AC14(0.5,-9.5) AC15(1.5,-9.5) AC16(2.5,-9.5) AC17(3.5,-9.5) AC18(4.5,-9.5) AC19(5.5,-9.5) AC20(6.5,-9.5) AC21(7.5,-9.5) AC22(8.5,-9.5) AC23(9.5,-9.5) AC24(10.5,-9.5) AC25(11.5,-9.5) AC26(12.5,-9.5) AD1(-12.5,-10.5) AD2(-11.5,-10.5) AD3(-10.5,-10.5) AD4(-9.5,-10.5) AD5(-8.5,-10.5) AD6(-7.5,-10.5) AD7(-6.5,-10.5) AD8(-5.5,-10.5) AD9(-4.5,-10.5) AD10(-3.5,-10.5) AD11(-2.5,-10.5) AD12(-1.5,-10.5) AD13(-0.5,-10.5) AD14(0.5,-10.5) AD15(1.5,-10.5) AD16(2.5,-10.5) AD17(3.5,-10.5) AD18(4.5,-10.5) AD19(5.5,-10.5) AD20(6.5,-10.5) AD21(7.5,-10.5) AD22(8.5,-10.5) AD23(9.5,-10.5) AD24(10.5,-10.5) AD25(11.5,-10.5) AD26(12.5,-10.5) AE1(-12.5,-11.5) AE2(-11.5,-11.5) AE3(-10.5,-11.5) AE4(-9.5,-11.5) AE5(-8.5,-11.5) AE6(-7.5,-11.5) AE7(-6.5,-11.5) AE8(-5.5,-11.5) AE9(-4.5,-11.5) AE10(-3.5,-11.5) AE11(-2.5,-11.5) AE12(-1.5,-11.5) AE13(-0.5,-11.5) AE14(0.5,-11.5) AE15(1.5,-11.5) AE16(2.5,-11.5) AE17(3.5,-11.5) AE18(4.5,-11.5) AE19(5.5,-11.5) AE20(6.5,-11.5) AE21(7.5,-11.5) AE22(8.5,-11.5) AE23(9.5,-11.5) AE24(10.5,-11.5) AE25(11.5,-11.5) AE26(12.5,-11.5) AF2(-11.5,-12.5) AF3(-10.5,-12.5) AF4(-9.5,-12.5) AF5(-8.5,-12.5) AF6(-7.5,-12.5) AF7(-6.5,-12.5) AF8(-5.5,-12.5) AF9(-4.5,-12.5) AF10(-3.5,-12.5) AF11(-2.5,-12.5) AF12(-1.5,-12.5) AF13(-0.5,-12.5) AF14(0.5,-12.5) AF15(1.5,-12.5) AF16(2.5,-12.5) AF17(3.5,-12.5) AF18(4.5,-12.5) AF19(5.5,-12.5) AF20(6.5,-12.5) AF21(7.5,-12.5) AF22(8.5,-12.5) AF23(9.5,-12.5) AF24(10.5,-12.5) AF25(11.5,-12.5) B1(-12.5,11.5) B2(-11.5,11.5) B3(-10.5,11.5) B4(-9.5,11.5) B5(-8.5,11.5) B6(-7.5,11.5) B7(-6.5,11.5) B8(-5.5,11.5) B9(-4.5,11.5) B10(-3.5,11.5) B11(-2.5,11.5) B12(-1.5,11.5) B13(-0.5,11.5) B14(0.5,11.5) B15(1.5,11.5) B16(2.5,11.5) B17(3.5,11.5) B18(4.5,11.5) B19(5.5,11.5) B20(6.5,11.5) B21(7.5,11.5) B22(8.5,11.5) B23(9.5,11.5) B24(10.5,11.5) B25(11.5,11.5) B26(12.5,11.5) C1(-12.5,10.5) C2(-11.5,10.5) C3(-10.5,10.5) C4(-9.5,10.5) C5(-8.5,10.5) C6(-7.5,10.5) C7(-6.5,10.5) C8(-5.5,10.5) C9(-4.5,10.5) C10(-3.5,10.5) C11(-2.5,10.5) C12(-1.5,10.5) C13(-0.5,10.5) C14(0.5,10.5) C15(1.5,10.5) C16(2.5,10.5) C17(3.5,10.5) C18(4.5,10.5) C19(5.5,10.5) C20(6.5,10.5) C21(7.5,10.5) C22(8.5,10.5) C23(9.5,10.5) C24(10.5,10.5) C25(11.5,10.5) C26(12.5,10.5) D1(-12.5,9.5) D2(-11.5,9.5) D3(-10.5,9.5) D4(-9.5,9.5) D5(-8.5,9.5) D6(-7.5,9.5) D7(-6.5,9.5) D8(-5.5,9.5) D9(-4.5,9.5) D10(-3.5,9.5) D11(-2.5,9.5) D12(-1.5,9.5) D13(-0.5,9.5) D14(0.5,9.5) D15(1.5,9.5) D16(2.5,9.5) D17(3.5,9.5) D18(4.5,9.5) D19(5.5,9.5) D20(6.5,9.5) D21(7.5,9.5) D22(8.5,9.5) D23(9.5,9.5) D24(10.5,9.5) D25(11.5,9.5) D26(12.5,9.5) E1(-12.5,8.5) E2(-11.5,8.5) E3(-10.5,8.5) E4(-9.5,8.5) E5(-8.5,8.5) E6(-7.5,8.5) E7(-6.5,8.5) E8(-5.5,8.5) E9(-4.5,8.5) E10(-3.5,8.5) E11(-2.5,8.5) E12(-1.5,8.5) E13(-0.5,8.5) E14(0.5,8.5) E15(1.5,8.5) E16(2.5,8.5) E17(3.5,8.5) E18(4.5,8.5) E19(5.5,8.5) E20(6.5,8.5) E21(7.5,8.5) E22(8.5,8.5) E23(9.5,8.5) E24(10.5,8.5) E25(11.5,8.5) E26(12.5,8.5) F1(-12.5,7.5) F2(-11.5,7.5) F3(-10.5,7.5) F4(-9.5,7.5) F5(-8.5,7.5) F6(-7.5,7.5) F7(-6.5,7.5) F8(-5.5,7.5) F9(-4.5,7.5) F10(-3.5,7.5) F11(-2.5,7.5) F12(-1.5,7.5) F13(-0.5,7.5) F14(0.5,7.5) F15(1.5,7.5) F16(2.5,7.5) F17(3.5,7.5) F18(4.5,7.5) F19(5.5,7.5) F20(6.5,7.5) F21(7.5,7.5) F22(8.5,7.5) F23(9.5,7.5) F24(10.5,7.5) F25(11.5,7.5) F26(12.5,7.5) G1(-12.5,6.5) G2(-11.5,6.5) G3(-10.5,6.5) G4(-9.5,6.5) G5(-8.5,6.5) G6(-7.5,6.5) G7(-6.5,6.5) G8(-5.5,6.5) G9(-4.5,6.5) G10(-3.5,6.5) G11(-2.5,6.5) G12(-1.5,6.5) G13(-0.5,6.5) G14(0.5,6.5) G15(1.5,6.5) G16(2.5,6.5) G17(3.5,6.5) G18(4.5,6.5) G19(5.5,6.5) G20(6.5,6.5) G21(7.5,6.5) G22(8.5,6.5) G23(9.5,6.5) G24(10.5,6.5) G25(11.5,6.5) G26(12.5,6.5) H1(-12.5,5.5) H2(-11.5,5.5) H3(-10.5,5.5) H4(-9.5,5.5) H5(-8.5,5.5) H6(-7.5,5.5) H7(-6.5,5.5) H8(-5.5,5.5) H9(-4.5,5.5) H10(-3.5,5.5) H11(-2.5,5.5) H12(-1.5,5.5) H13(-0.5,5.5) H14(0.5,5.5) H15(1.5,5.5) H16(2.5,5.5) H17(3.5,5.5) H18(4.5,5.5) H19(5.5,5.5) H20(6.5,5.5) H21(7.5,5.5) H22(8.5,5.5) H23(9.5,5.5) H24(10.5,5.5) H25(11.5,5.5) H26(12.5,5.5) J1(-12.5,4.5) J2(-11.5,4.5) J3(-10.5,4.5) J4(-9.5,4.5) J5(-8.5,4.5) J6(-7.5,4.5) J7(-6.5,4.5) J8(-5.5,4.5) J9(-4.5,4.5) J10(-3.5,4.5) J11(-2.5,4.5) J12(-1.5,4.5) J13(-0.5,4.5) J14(0.5,4.5) J15(1.5,4.5) J16(2.5,4.5) J17(3.5,4.5) J18(4.5,4.5) J19(5.5,4.5) J20(6.5,4.5) J21(7.5,4.5) J22(8.5,4.5) J23(9.5,4.5) J24(10.5,4.5) J25(11.5,4.5) J26(12.5,4.5) K1(-12.5,3.5) K2(-11.5,3.5) K3(-10.5,3.5) K4(-9.5,3.5) K5(-8.5,3.5) K6(-7.5,3.5) K7(-6.5,3.5) K8(-5.5,3.5) K9(-4.5,3.5) K10(-3.5,3.5) K11(-2.5,3.5) K12(-1.5,3.5) K13(-0.5,3.5) K14(0.5,3.5) K15(1.5,3.5) K16(2.5,3.5) K17(3.5,3.5) K18(4.5,3.5) K19(5.5,3.5) K20(6.5,3.5) K21(7.5,3.5) K22(8.5,3.5) K23(9.5,3.5) K24(10.5,3.5) K25(11.5,3.5) K26(12.5,3.5) L1(-12.5,2.5) L2(-11.5,2.5) L3(-10.5,2.5) L4(-9.5,2.5) L5(-8.5,2.5) L6(-7.5,2.5) L7(-6.5,2.5) L8(-5.5,2.5) L9(-4.5,2.5) L10(-3.5,2.5) L11(-2.5,2.5) L12(-1.5,2.5) L13(-0.5,2.5) L14(0.5,2.5) L15(1.5,2.5) L16(2.5,2.5) L17(3.5,2.5) L18(4.5,2.5) L19(5.5,2.5) L20(6.5,2.5) L21(7.5,2.5) L22(8.5,2.5) L23(9.5,2.5) L24(10.5,2.5) L25(11.5,2.5) L26(12.5,2.5) M1(-12.5,1.5) M2(-11.5,1.5) M3(-10.5,1.5) M4(-9.5,1.5) M5(-8.5,1.5) M6(-7.5,1.5) M7(-6.5,1.5) M8(-5.5,1.5) M9(-4.5,1.5) M10(-3.5,1.5) M11(-2.5,1.5) M12(-1.5,1.5) M13(-0.5,1.5) M14(0.5,1.5) M15(1.5,1.5) M16(2.5,1.5) M17(3.5,1.5) M18(4.5,1.5) M19(5.5,1.5) M20(6.5,1.5) M21(7.5,1.5) M22(8.5,1.5) M23(9.5,1.5) M24(10.5,1.5) M25(11.5,1.5) M26(12.5,1.5) N1(-12.5,0.5) N2(-11.5,0.5) N3(-10.5,0.5) N4(-9.5,0.5) N5(-8.5,0.5) N6(-7.5,0.5) N7(-6.5,0.5) N8(-5.5,0.5) N9(-4.5,0.5) N10(-3.5,0.5) N11(-2.5,0.5) N12(-1.5,0.5) N13(-0.5,0.5) N14(0.5,0.5) N15(1.5,0.5) N16(2.5,0.5) N17(3.5,0.5) N18(4.5,0.5) N19(5.5,0.5) N20(6.5,0.5) N21(7.5,0.5) N22(8.5,0.5) N23(9.5,0.5) N24(10.5,0.5) N25(11.5,0.5) N26(12.5,0.5) P1(-12.5,-0.5) P2(-11.5,-0.5) P3(-10.5,-0.5) P4(-9.5,-0.5) P5(-8.5,-0.5) P6(-7.5,-0.5) P7(-6.5,-0.5) P8(-5.5,-0.5) P9(-4.5,-0.5) P10(-3.5,-0.5) P11(-2.5,-0.5) P12(-1.5,-0.5) P13(-0.5,-0.5) P14(0.5,-0.5) P15(1.5,-0.5) P16(2.5,-0.5) P17(3.5,-0.5) P18(4.5,-0.5) P19(5.5,-0.5) P20(6.5,-0.5) P21(7.5,-0.5) P22(8.5,-0.5) P23(9.5,-0.5) P24(10.5,-0.5) P25(11.5,-0.5) P26(12.5,-0.5) R1(-12.5,-1.5) R2(-11.5,-1.5) R3(-10.5,-1.5) R4(-9.5,-1.5) R5(-8.5,-1.5) R6(-7.5,-1.5) R7(-6.5,-1.5) R8(-5.5,-1.5) R9(-4.5,-1.5) R10(-3.5,-1.5) R11(-2.5,-1.5) R12(-1.5,-1.5) R13(-0.5,-1.5) R14(0.5,-1.5) R15(1.5,-1.5) R16(2.5,-1.5) R17(3.5,-1.5) R18(4.5,-1.5) R19(5.5,-1.5) R20(6.5,-1.5) R21(7.5,-1.5) R22(8.5,-1.5) R23(9.5,-1.5) R24(10.5,-1.5) R25(11.5,-1.5) R26(12.5,-1.5) T1(-12.5,-2.5) T2(-11.5,-2.5) T3(-10.5,-2.5) T4(-9.5,-2.5) T5(-8.5,-2.5) T6(-7.5,-2.5) T7(-6.5,-2.5) T8(-5.5,-2.5) T9(-4.5,-2.5) T10(-3.5,-2.5) T11(-2.5,-2.5) T12(-1.5,-2.5) T13(-0.5,-2.5) T14(0.5,-2.5) T15(1.5,-2.5) T16(2.5,-2.5) T17(3.5,-2.5) T18(4.5,-2.5) T19(5.5,-2.5) T20(6.5,-2.5) T21(7.5,-2.5) T22(8.5,-2.5) T23(9.5,-2.5) T24(10.5,-2.5) T25(11.5,-2.5) T26(12.5,-2.5) U1(-12.5,-3.5) U2(-11.5,-3.5) U3(-10.5,-3.5) U4(-9.5,-3.5) U5(-8.5,-3.5) U6(-7.5,-3.5) U7(-6.5,-3.5) U8(-5.5,-3.5) U9(-4.5,-3.5) U10(-3.5,-3.5) U11(-2.5,-3.5) U12(-1.5,-3.5) U13(-0.5,-3.5) U14(0.5,-3.5) U15(1.5,-3.5) U16(2.5,-3.5) U17(3.5,-3.5) U18(4.5,-3.5) U19(5.5,-3.5) U20(6.5,-3.5) U21(7.5,-3.5) U22(8.5,-3.5) U23(9.5,-3.5) U24(10.5,-3.5) U25(11.5,-3.5) U26(12.5,-3.5) V1(-12.5,-4.5) V2(-11.5,-4.5) V3(-10.5,-4.5) V4(-9.5,-4.5) V5(-8.5,-4.5) V6(-7.5,-4.5) V7(-6.5,-4.5) V8(-5.5,-4.5) V9(-4.5,-4.5) V10(-3.5,-4.5) V11(-2.5,-4.5) V12(-1.5,-4.5) V13(-0.5,-4.5) V14(0.5,-4.5) V15(1.5,-4.5) V16(2.5,-4.5) V17(3.5,-4.5) V18(4.5,-4.5) V19(5.5,-4.5) V20(6.5,-4.5) V21(7.5,-4.5) V22(8.5,-4.5) V23(9.5,-4.5) V24(10.5,-4.5) V25(11.5,-4.5) V26(12.5,-4.5) W1(-12.5,-5.5) W2(-11.5,-5.5) W3(-10.5,-5.5) W4(-9.5,-5.5) W5(-8.5,-5.5) W6(-7.5,-5.5) W7(-6.5,-5.5) W8(-5.5,-5.5) W9(-4.5,-5.5) W10(-3.5,-5.5) W11(-2.5,-5.5) W12(-1.5,-5.5) W13(-0.5,-5.5) W14(0.5,-5.5) W15(1.5,-5.5) W16(2.5,-5.5) W17(3.5,-5.5) W18(4.5,-5.5) W19(5.5,-5.5) W20(6.5,-5.5) W21(7.5,-5.5) W22(8.5,-5.5) W23(9.5,-5.5) W24(10.5,-5.5) W25(11.5,-5.5) W26(12.5,-5.5) Y1(-12.5,-6.5) Y2(-11.5,-6.5) Y3(-10.5,-6.5) Y4(-9.5,-6.5) Y5(-8.5,-6.5) Y6(-7.5,-6.5) Y7(-6.5,-6.5) Y8(-5.5,-6.5) Y9(-4.5,-6.5) Y10(-3.5,-6.5) Y11(-2.5,-6.5) Y12(-1.5,-6.5) Y13(-0.5,-6.5) Y14(0.5,-6.5) Y15(1.5,-6.5) Y16(2.5,-6.5) Y17(3.5,-6.5) Y18(4.5,-6.5) Y19(5.5,-6.5) Y20(6.5,-6.5) Y21(7.5,-6.5) Y22(8.5,-6.5) Y23(9.5,-6.5) Y24(10.5,-6.5) Y25(11.5,-6.5) Y26(12.5,-6.5)
  round 1 on Mech7 paste-0.55 mask+1: FID1(-15,15) FID1(15,-15)
  round 1 smd paste+0 mask+0.635: FID1(-15,15) FID1(15,-15)
  Top Layer keep-out circle w0.2: c15,-15 r1
  Top Layer keep-out circle w0.2: c-15,15 r1
  silkscreen extent -14.27,-13.5 13.5,13.5, body extent -13.59,-13.46 13.46,13.54, height 2.35
CAPC1005-STAR [mm] "Chip Capacitor 1005"
  rect 0.6x0.6 smd: 1(-0.525,0) 2(0.525,0)
  silkscreen extent -0.05,-0.38 0.05,0.38, body extent -0.57,-0.3 0.57,0.3, height 0.4
CAPC1608-STAR [mm] "Capacitor SMD 0603 (1608)"
  rect 0.9x0.8 smd: 1(-0.8,0) 2(0.8,0)
  silkscreen extent 0,-0.4 0,0.4, body extent -1.11,-0.41 1.1,0.39, height 0.8
CAPC2012-STAR [mm] "0805 Capacitor SMD - Startronics"
  rect 1x1.25 smd: 1(-1,0) 2(1,0)
  silkscreen extent -0.4,-1 0.4,1, body extent -0.98,-0.64 0.87,0.6, height 0.8
CAPC3216-STAR [mm] "Capacitor 1206 (3216) for Startronics"
  rect 1x1.6 smd: 1(-1.45,0) 2(1.45,0)
  silkscreen extent -0.62,-1.1 0.62,1.1, body extent -1.64,-0.89 1.63,0.86, height 0.9
CAPC3225-STAR [mm] "1210 Capacitor SMD - Startronics"
  rect 1x2.75 smd: 1(-1.5,0) 2(1.5,0)
  silkscreen extent -0.7,-1.5 0.7,1.5, body extent -1.94,-1.2 1.89,1.29, height 1.5
CAPC7343-STAR [mm] "Capcacitor SMD 7.3 x 4.3mm (D-Case)"
  rect 2.6x2.4 smd: 1(-3.202,0.007) 2(3.198,0.007)
  silkscreen extent -5.33,-2.39 5.08,2.41, body extent -3.49,-2.03 3.51,2.04, height 4.05
IND-EPCOS-SMD-B82559 [mm]
  rect 4.4x10.4 smd: 1(0,0) 2(8.4,0)
  silkscreen extent -2.5,-5.5 11,5.5, body extent -2.55,-5.3 10.9,5.6, height 4.95
INDC2012-STAR [mm] "0805 Inductor SMD - Startronics"
  rect 1x1.25 smd: 1(-1,0) 2(1,0)
  silkscreen extent -0.4,-1 0.4,1, body extent -0.9,-0.64 1,0.6, height 0.8
LEAD_FREE_S [mil]
  silkscreen extent -125,-125 125,125
LED2012-STAR [mm] "0805 LED SMD - Startronics"
  rect 1x1.25 smd: 1(1,0) 2(-1,0)
  silkscreen extent -2.27,-1 1.8,1, body extent -1.6,-0.6 1.5,0.6, height 0.67
Logo-Altium [mil]
  silkscreen extent -1025,-99 -556,102
MOUNTING_HOLE_3MM [mm] "Non-plated mounting hole for 3mm screw"
  round 3.8 hole 3.4 mask+0.2: MOUNT(0,0)
  Top Layer circle w1: c0,0 r2.3
  Top Layer region: -2.8,-2.8 2.8,-2.8 2.8,2.8 -2.8,2.8
  Top Layer keep-out region: -3.3,-3.3 3.3,-3.3 3.3,3.3 -3.3,3.3
  Bottom Layer region: -2.8,-2.8 2.8,-2.8 2.8,2.8 -2.8,2.8
  Bottom Layer keep-out region: -3.3,-3.3 3.3,-3.3 3.3,3.3 -3.3,3.3
  Keep-Out Layer circle w1.2: c0,0 r2.5
NETTIE-SMT2-8X8 [mm]
  rect 0.4x0.2 smd paste-0.11 mask-0.11: 1(-0.891,-0.006) 2(-0.691,-0.006)
RESC1005-STAR [mm] "Chip Inductor 1005"
  rect 0.575x0.6 smd: 1(-0.538,0) 2(0.538,0)
  silkscreen extent -0.05,-0.38 0.05,0.38, body extent -0.71,-0.25 0.72,0.26, height 0.25
RESNET-1005X4 [mm] "Resistor network 4 x 1005 (0402)"
  rect 0.3x0.83 smd: 1(-0.75,-0.64) 2(-0.25,-0.64) 3(0.25,-0.64) 4(0.75,-0.64) 5(0.75,0.64) 6(0.25,0.64) 7(-0.25,0.64) 8(-0.75,0.64)
  silkscreen extent -1.15,-1 1.15,1, body extent -0.92,-0.84 1.04,0.81, height 0.4
SOP63P602-16 [mil]
  rect 82x16 smd: 1(-116,87.5) 2(-116,62) 3(-116,37.5) 4(-116,12.5) 5(-116,-12.5) 6(-116,-37.5) 7(-116,-62.5) 8(-116,-87.5) 9(116,-87.5) 10(116,-62.5) 11(116,-37.5) 12(116,-12.5) 13(116,12.5) 14(116,37.5) 15(116,62.5) 16(116,87.5)
  silkscreen extent -100,-100 60,125, body extent -107,-100 108,103, height 29
SOT95P280-5 [mm] "SOT-23/SC-74A; 5 Leads; Body 3.1 x 3 mm, inc. leads (LxW max)"
  rect 0.6x1.3 smd: 1(-0.95,-1.4) 2(0,-1.4) 3(0.95,-1.4) 4(0.95,1.4)
  rect 0.6x1.25 smd: 5(-0.95,1.4)
  silkscreen extent -1.55,-0.9 1.55,0.9, body extent -1.51,-1.49 1.52,1.52, height 0.8
TestPin [mil]
  round 60 hole 35.43: 1(0,0)
  silkscreen extent -41,-39 156,39
TSOC6 [mil]
  rect 25x71 smd: 1(-50,-75) 2(0,-75) 3(50,-75) 4(50,75) 5(0,75) 6(-50,75)
  silkscreen extent -115,-80 85,80
TSOP80P1176-44 [mm]
  rect 0.5x1.4 smd: 1(-8.4,-5.7) 2(-7.6,-5.7) 3(-6.8,-5.7) 4(-6,-5.7) 5(-5.2,-5.7) 6(-4.4,-5.7) 7(-3.6,-5.7) 8(-2.8,-5.7) 9(-2,-5.7) 10(-1.2,-5.7) 11(-0.4,-5.7) 12(0.4,-5.7) 13(1.2,-5.7) 14(2,-5.7) 15(2.8,-5.7) 16(3.6,-5.7) 17(4.4,-5.7) 18(5.2,-5.7) 19(6,-5.7) 20(6.8,-5.7) 21(7.6,-5.7) 22(8.4,-5.7) 23(8.4,5.7) 24(7.6,5.7) 25(6.8,5.7) 26(6,5.7) 27(5.2,5.7) 28(4.4,5.7) 29(3.6,5.7) 30(2.8,5.7) 31(2,5.7) 32(1.2,5.7) 33(0.4,5.7) 34(-0.4,5.7) 35(-1.2,5.7) 36(-2,5.7) 37(-2.8,5.7) 38(-3.6,5.7) 39(-4.4,5.7) 40(-5.2,5.7) 41(-6,5.7) 42(-6.8,5.7) 43(-7.6,5.7) 44(-8.4,5.7)
  silkscreen extent -9.29,-5.7 9.26,4.45, body extent -9.24,-5.95 9.26,5.84, height 1
TSOP80P1176-54 [mm] "Plastic Small Outline; 54 Leads; Body Width 10.16 mm"
  rect 0.5x1.4 smd: 1(-10.4,-5.7) 2(-9.6,-5.7) 3(-8.8,-5.7) 4(-8,-5.7) 5(-7.2,-5.7) 6(-6.4,-5.7) 7(-5.6,-5.7) 8(-4.8,-5.7) 9(-4,-5.7) 10(-3.2,-5.7) 11(-2.4,-5.7) 12(-1.6,-5.7) 13(-0.8,-5.7) 14(0,-5.7) 15(0.8,-5.7) 16(1.6,-5.7) 17(2.4,-5.7) 18(3.2,-5.7) 19(4,-5.7) 20(4.8,-5.7) 21(5.6,-5.7) 22(6.4,-5.7) 23(7.2,-5.7) 24(8,-5.7) 25(8.8,-5.7) 26(9.6,-5.7) 27(10.4,-5.7) 28(10.4,5.7) 29(9.6,5.7) 30(8.8,5.7) 31(8,5.7) 32(7.2,5.7) 33(6.4,5.7) 34(5.6,5.7) 35(4.8,5.7) 36(4,5.7) 37(3.2,5.7) 38(2.4,5.7) 39(1.6,5.7) 40(0.8,5.7) 41(0,5.7) 42(-0.8,5.7) 43(-1.6,5.7) 44(-2.4,5.7) 45(-3.2,5.7) 46(-4,5.7) 47(-4.8,5.7) 48(-5.6,5.7) 49(-6.4,5.7) 50(-7.2,5.7) 51(-8,5.7) 52(-8.8,5.7) 53(-9.6,5.7) 54(-10.4,5.7)
  silkscreen extent -11.33,-5.67 11.15,4.4, body extent -11.23,-5.96 11.19,5.97, height 1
